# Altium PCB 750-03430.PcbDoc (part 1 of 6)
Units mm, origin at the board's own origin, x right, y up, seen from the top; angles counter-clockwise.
Board outline 141.61 x 63.5 mm, 6 copper layers (Top Layer, L2, L3, L4, L5, Bottom Layer), stack 1.557 mm thick; 401 components, 285 nets, 1356 pads, 1712 vias.
Unrouted connection lines stored in the file: 45.
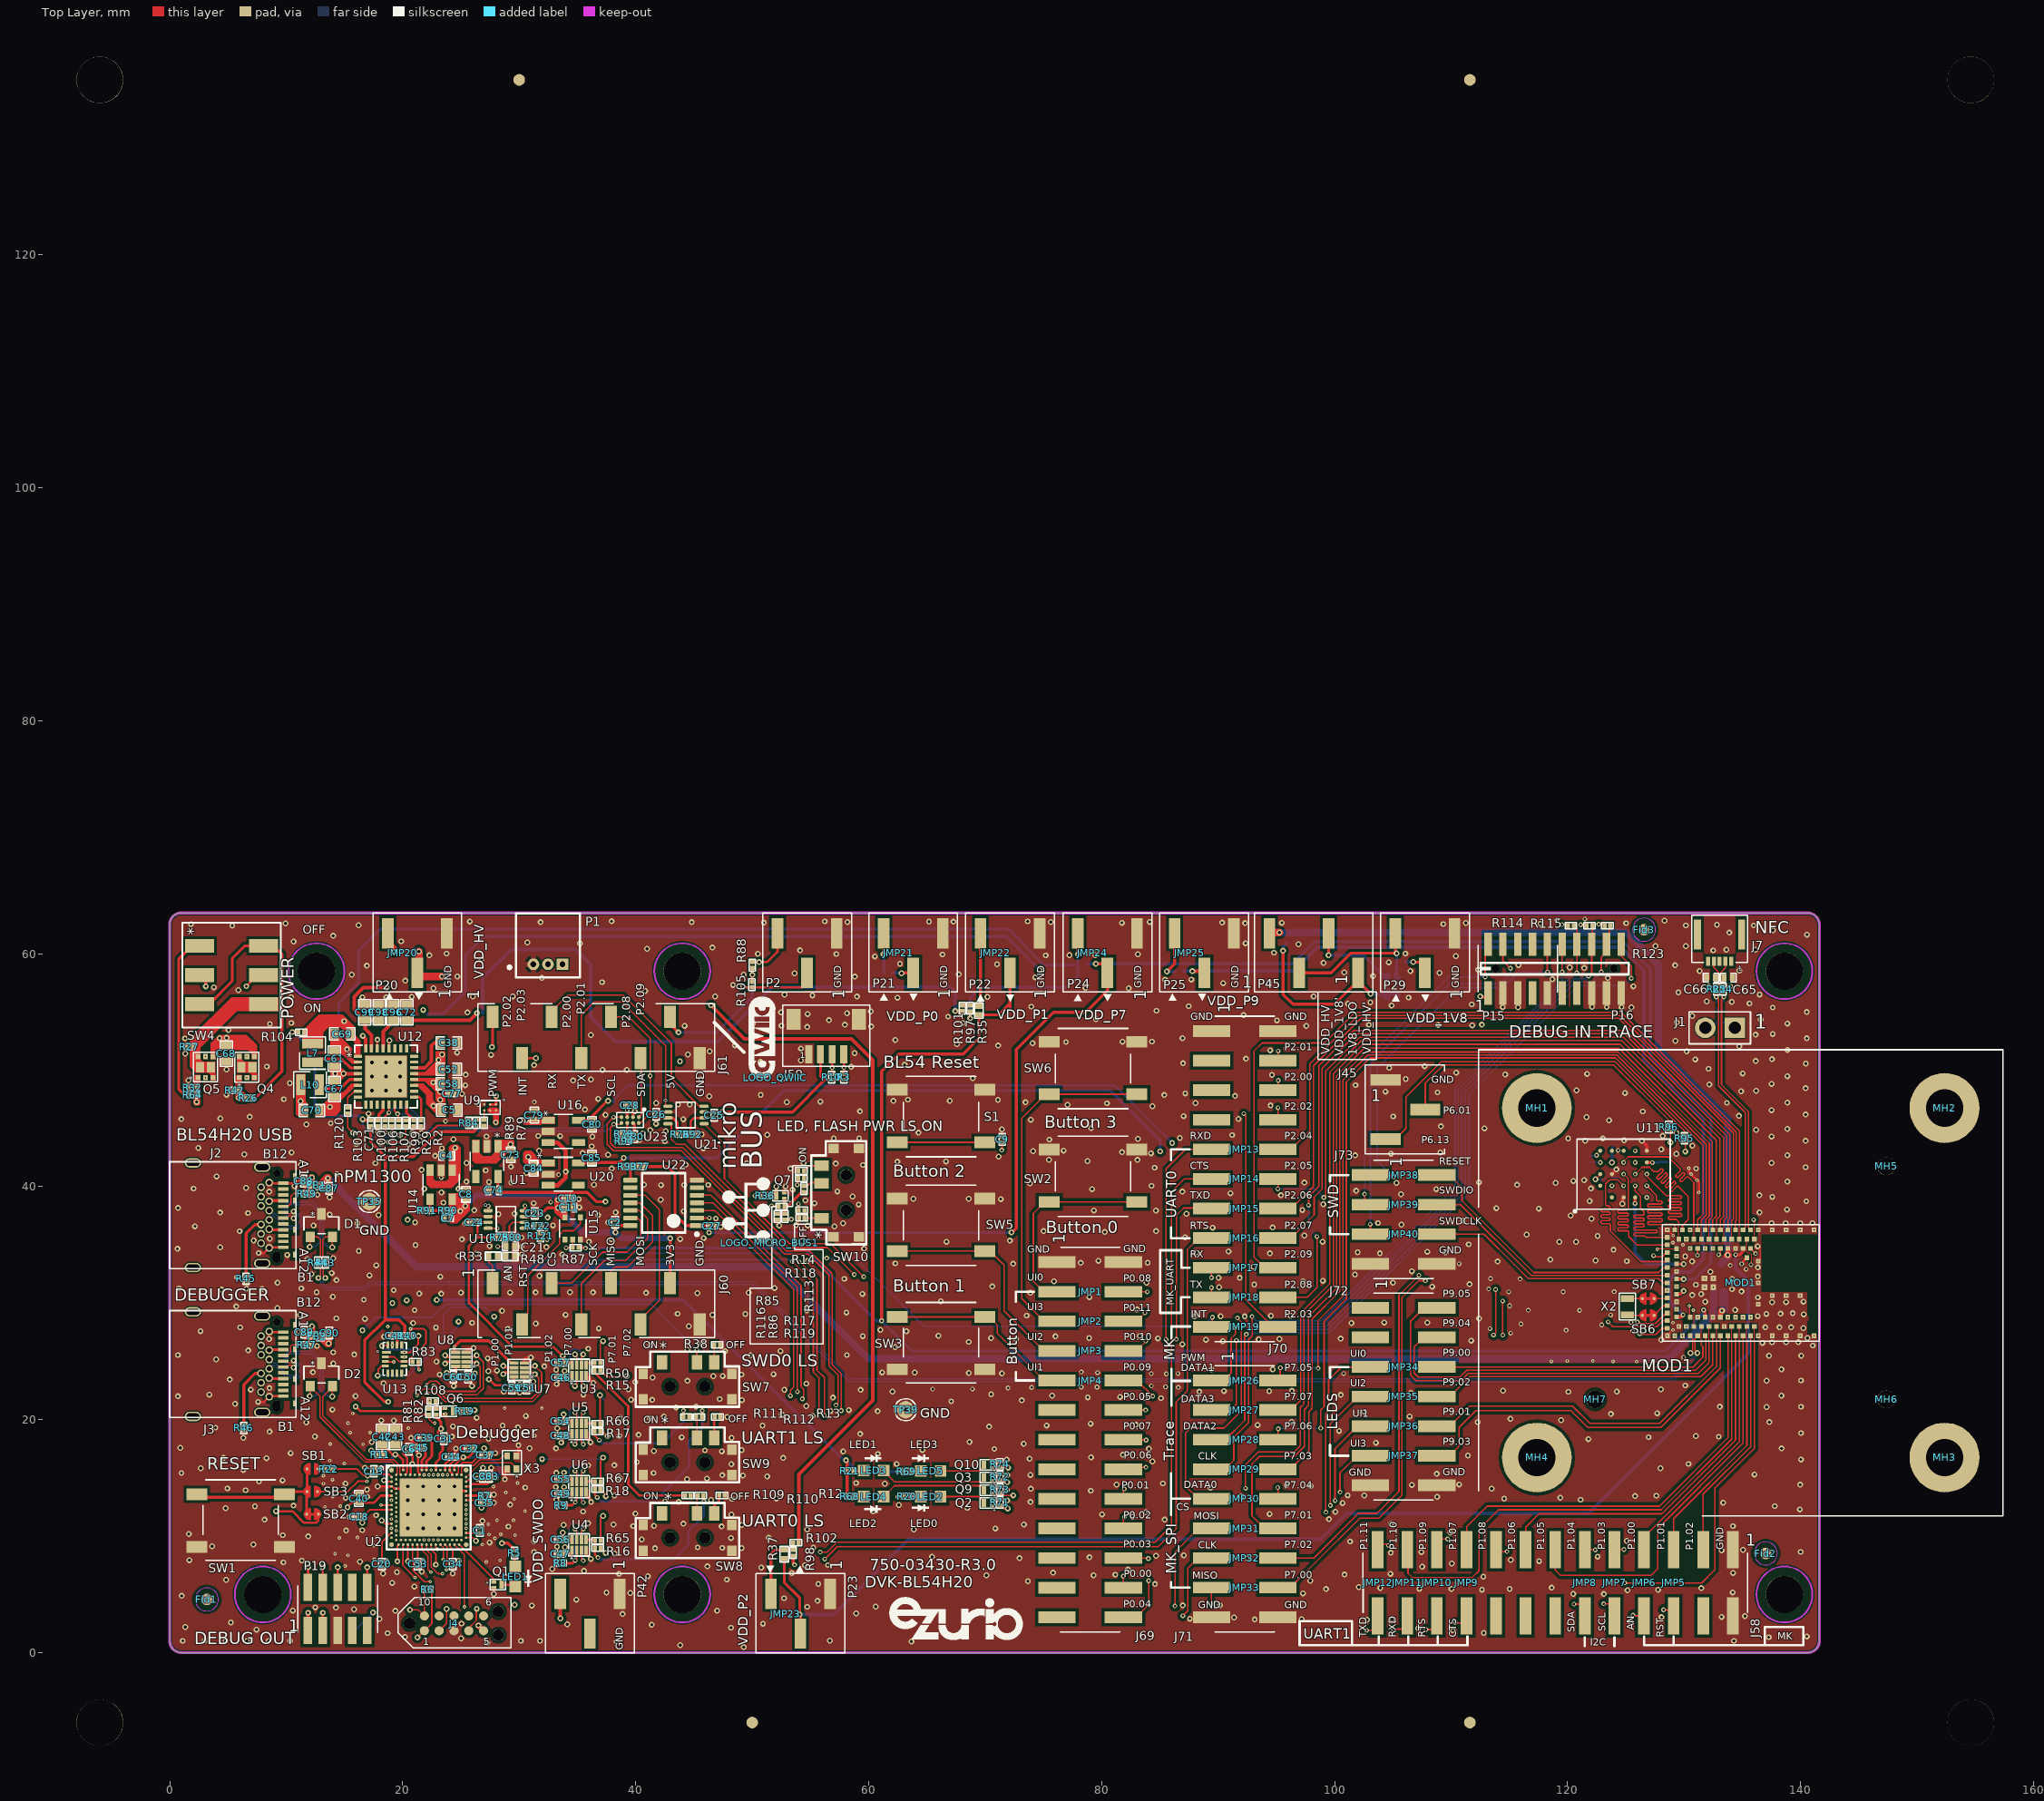
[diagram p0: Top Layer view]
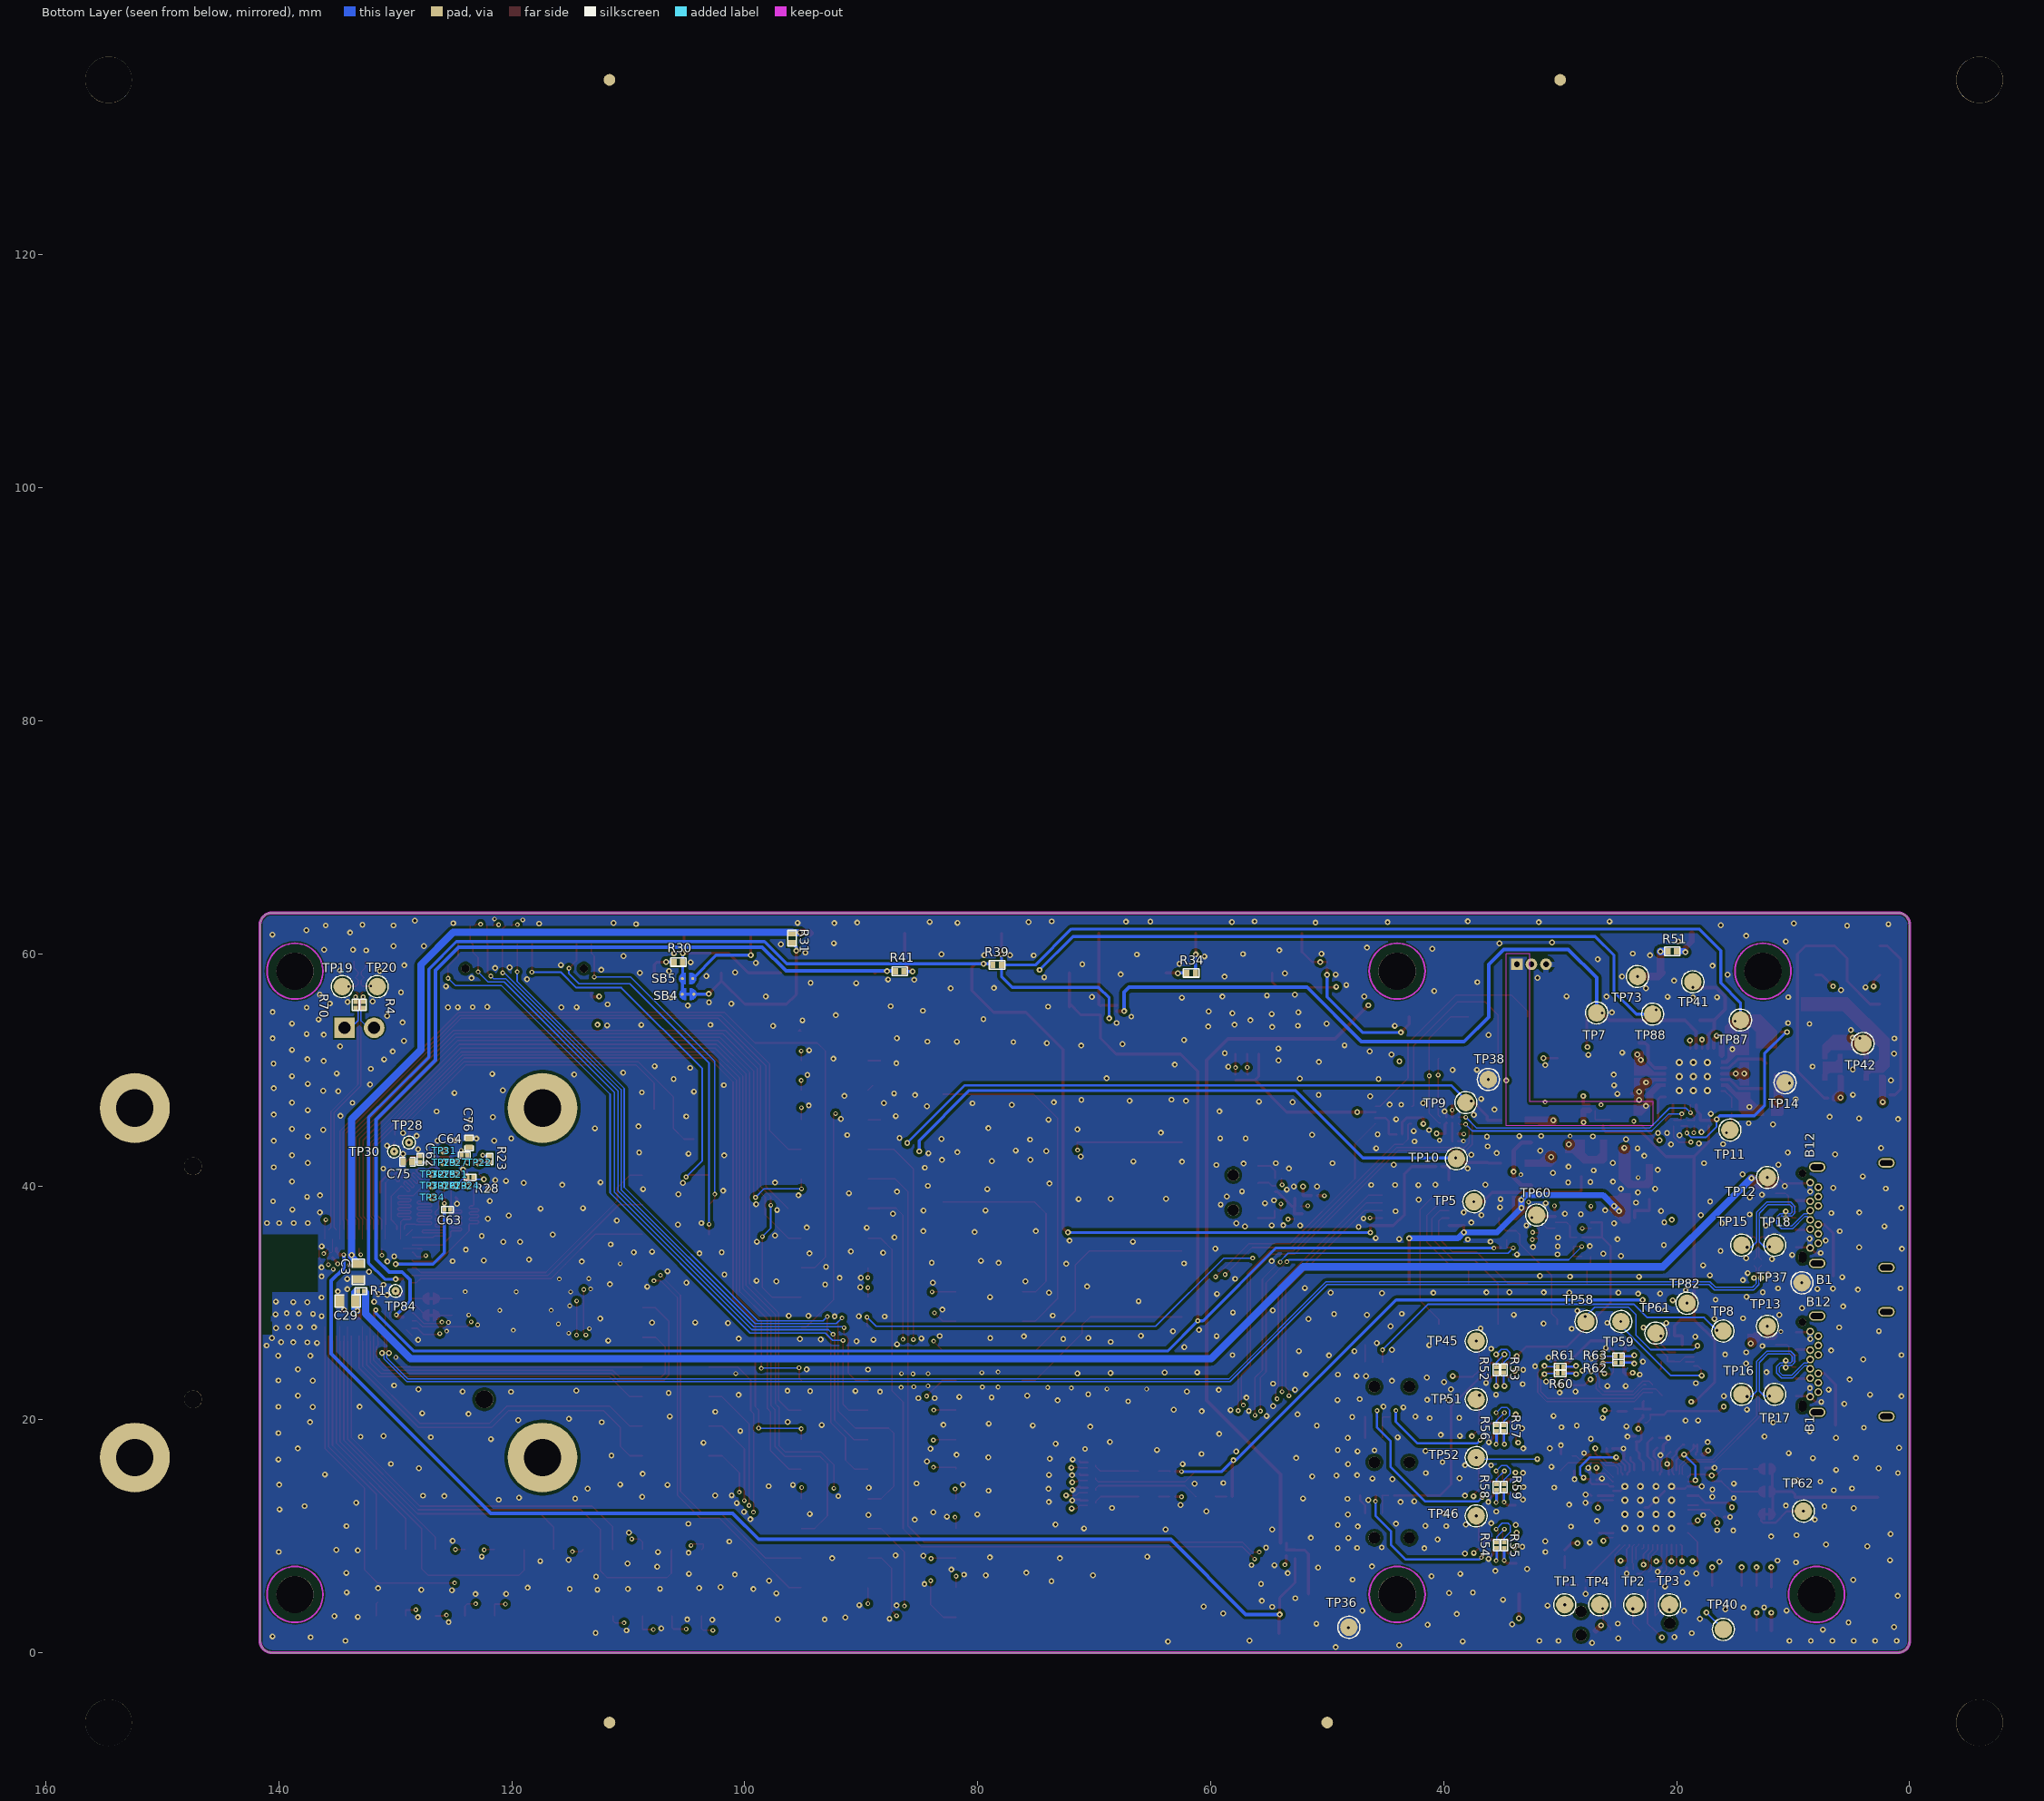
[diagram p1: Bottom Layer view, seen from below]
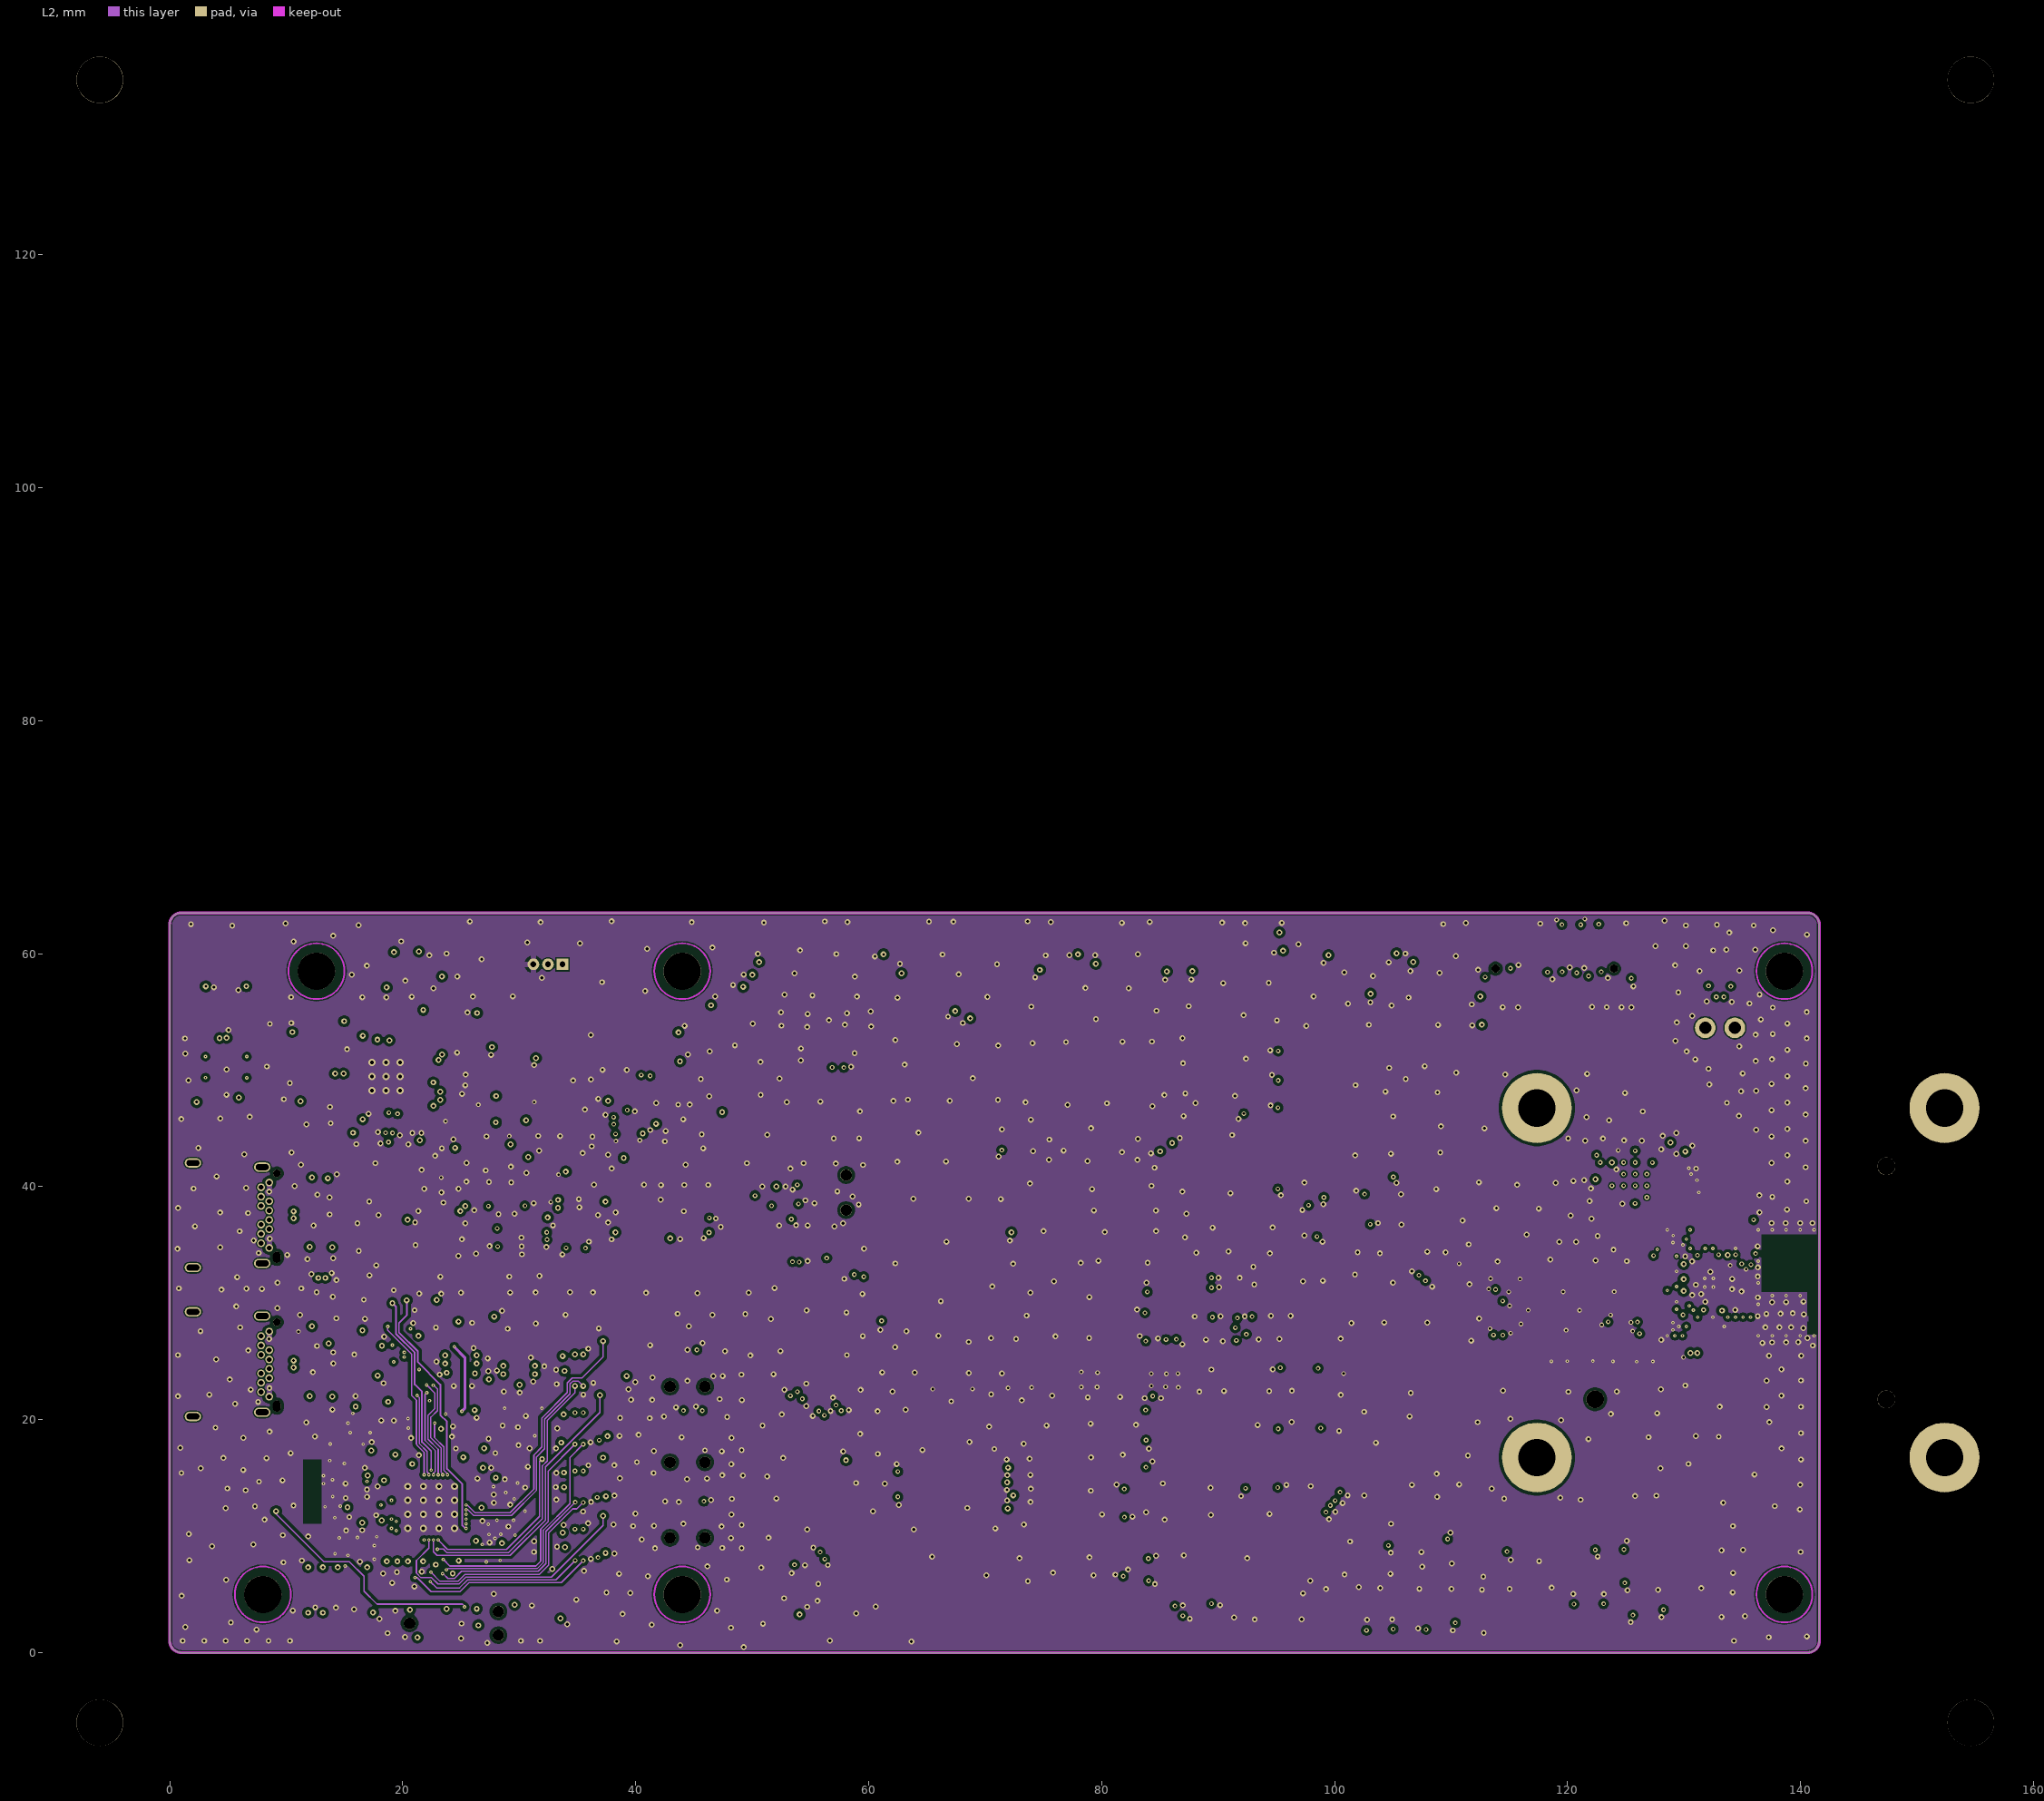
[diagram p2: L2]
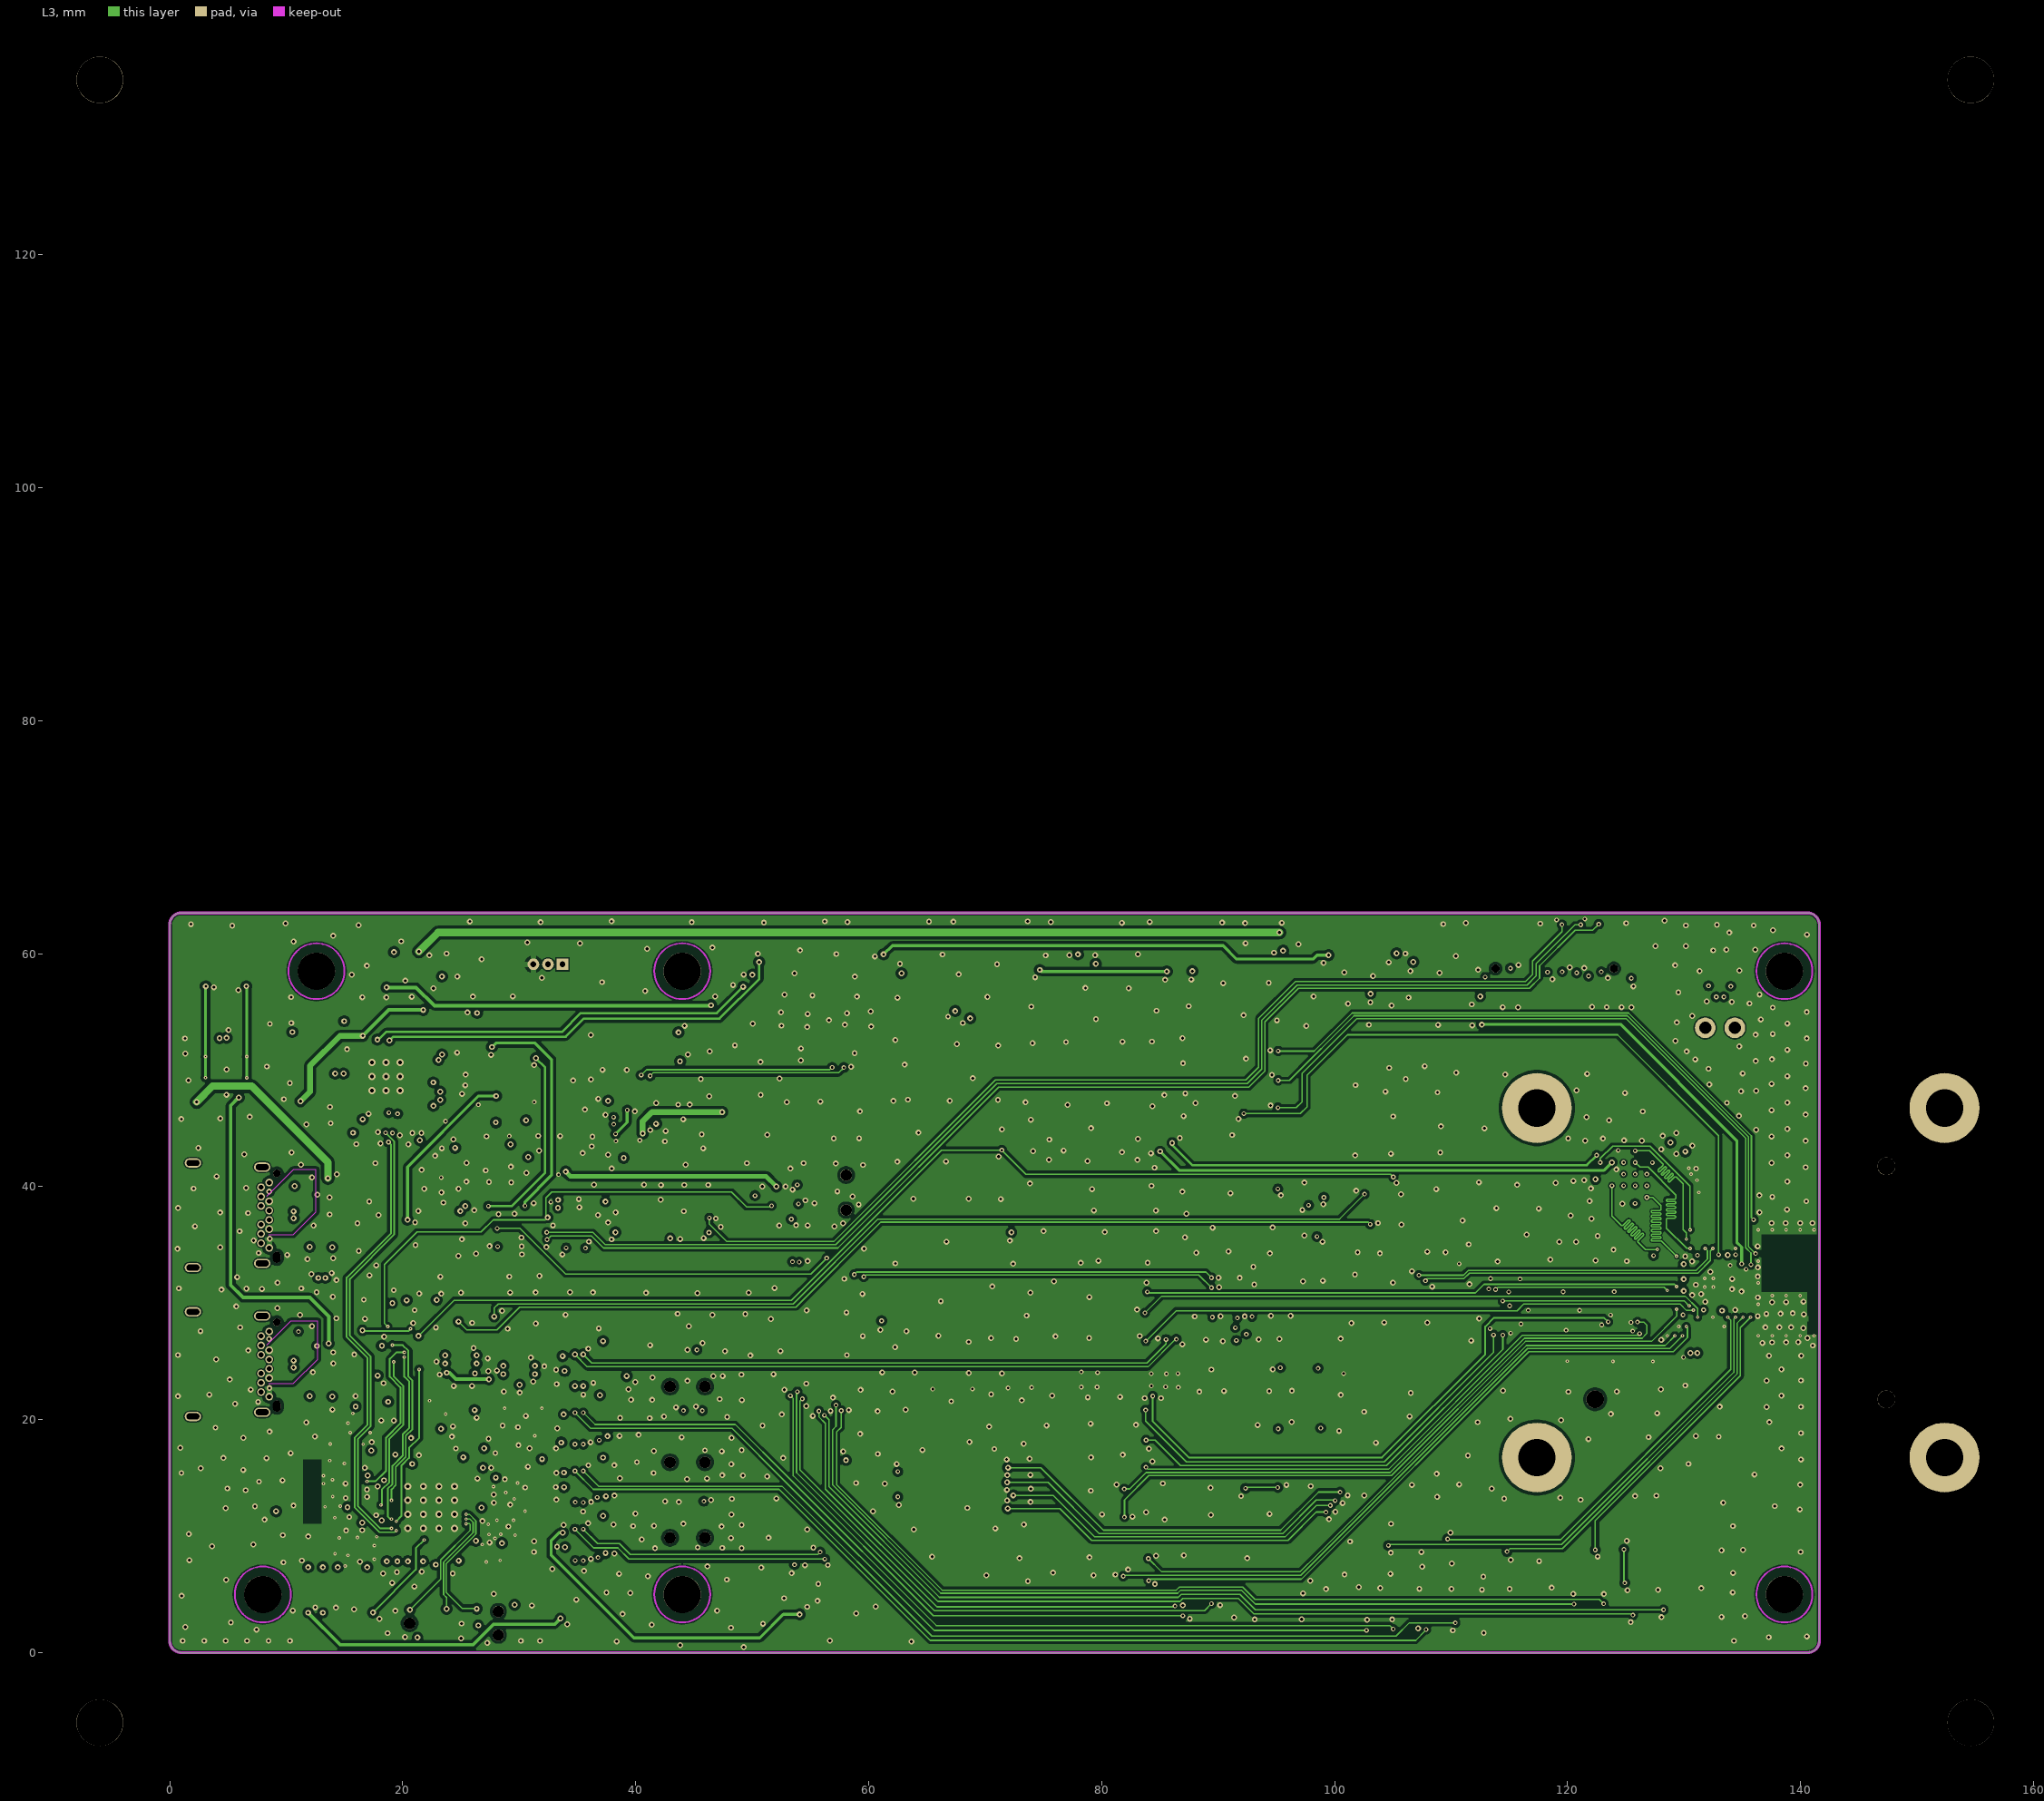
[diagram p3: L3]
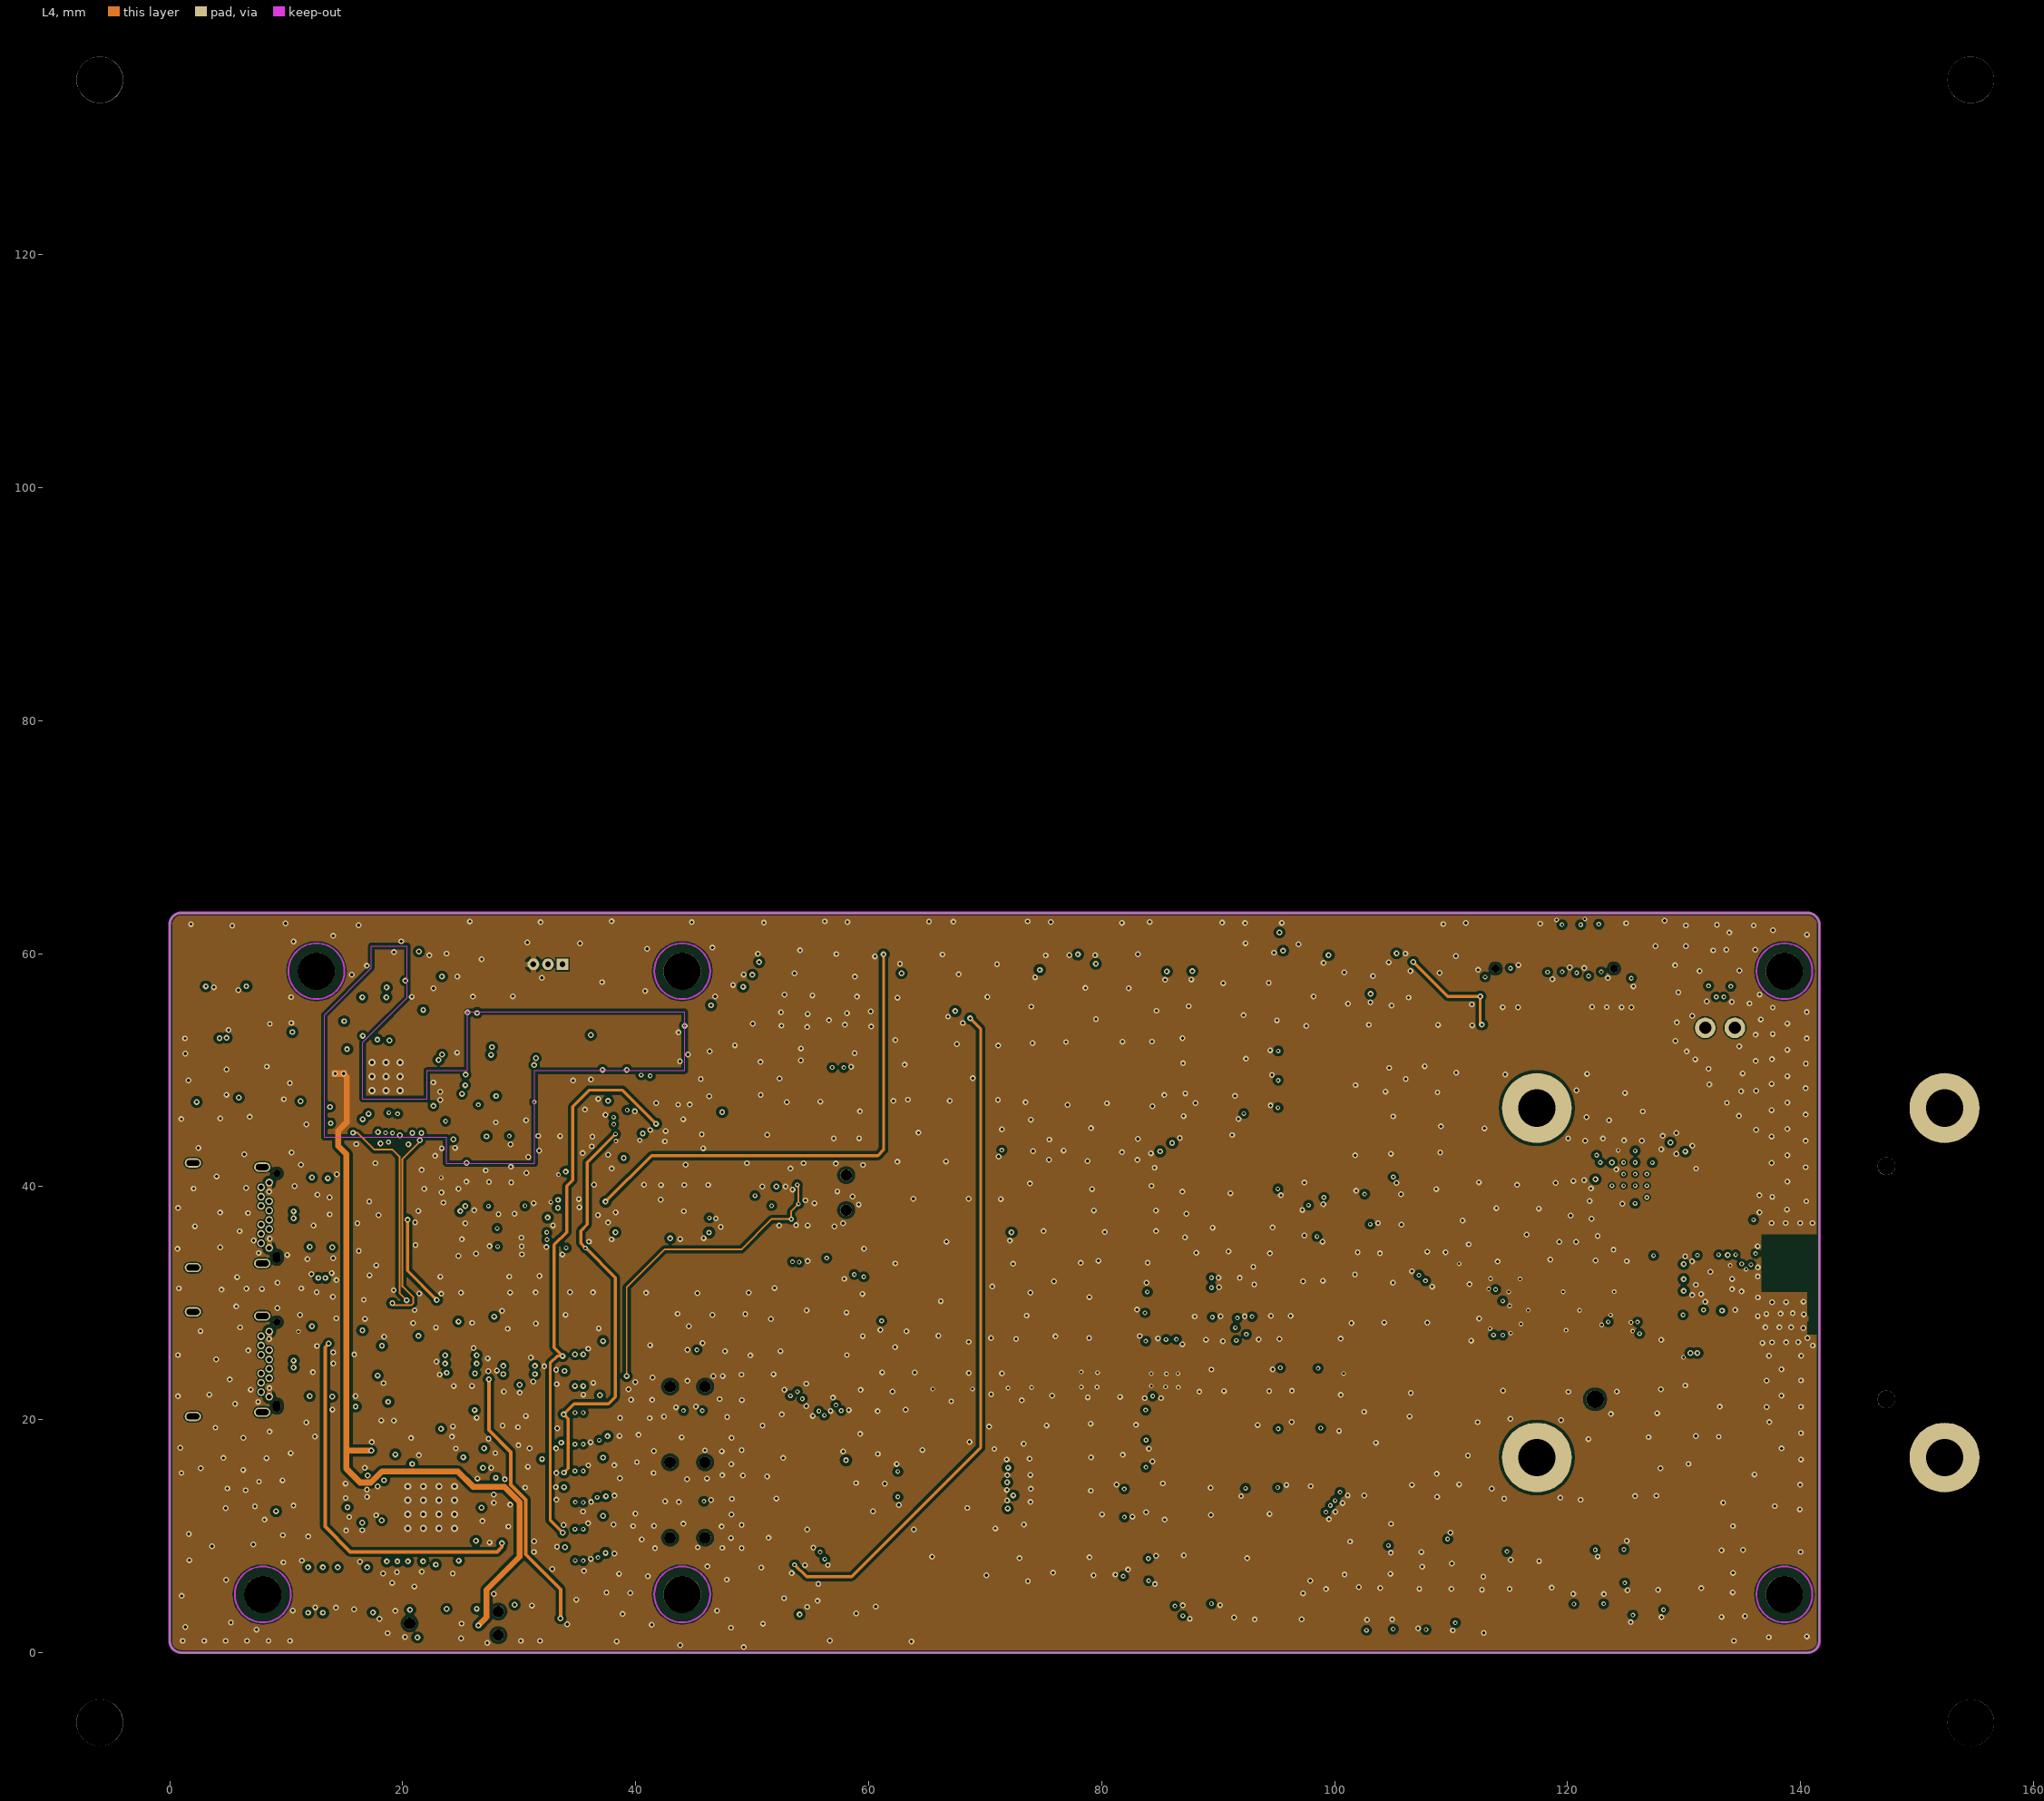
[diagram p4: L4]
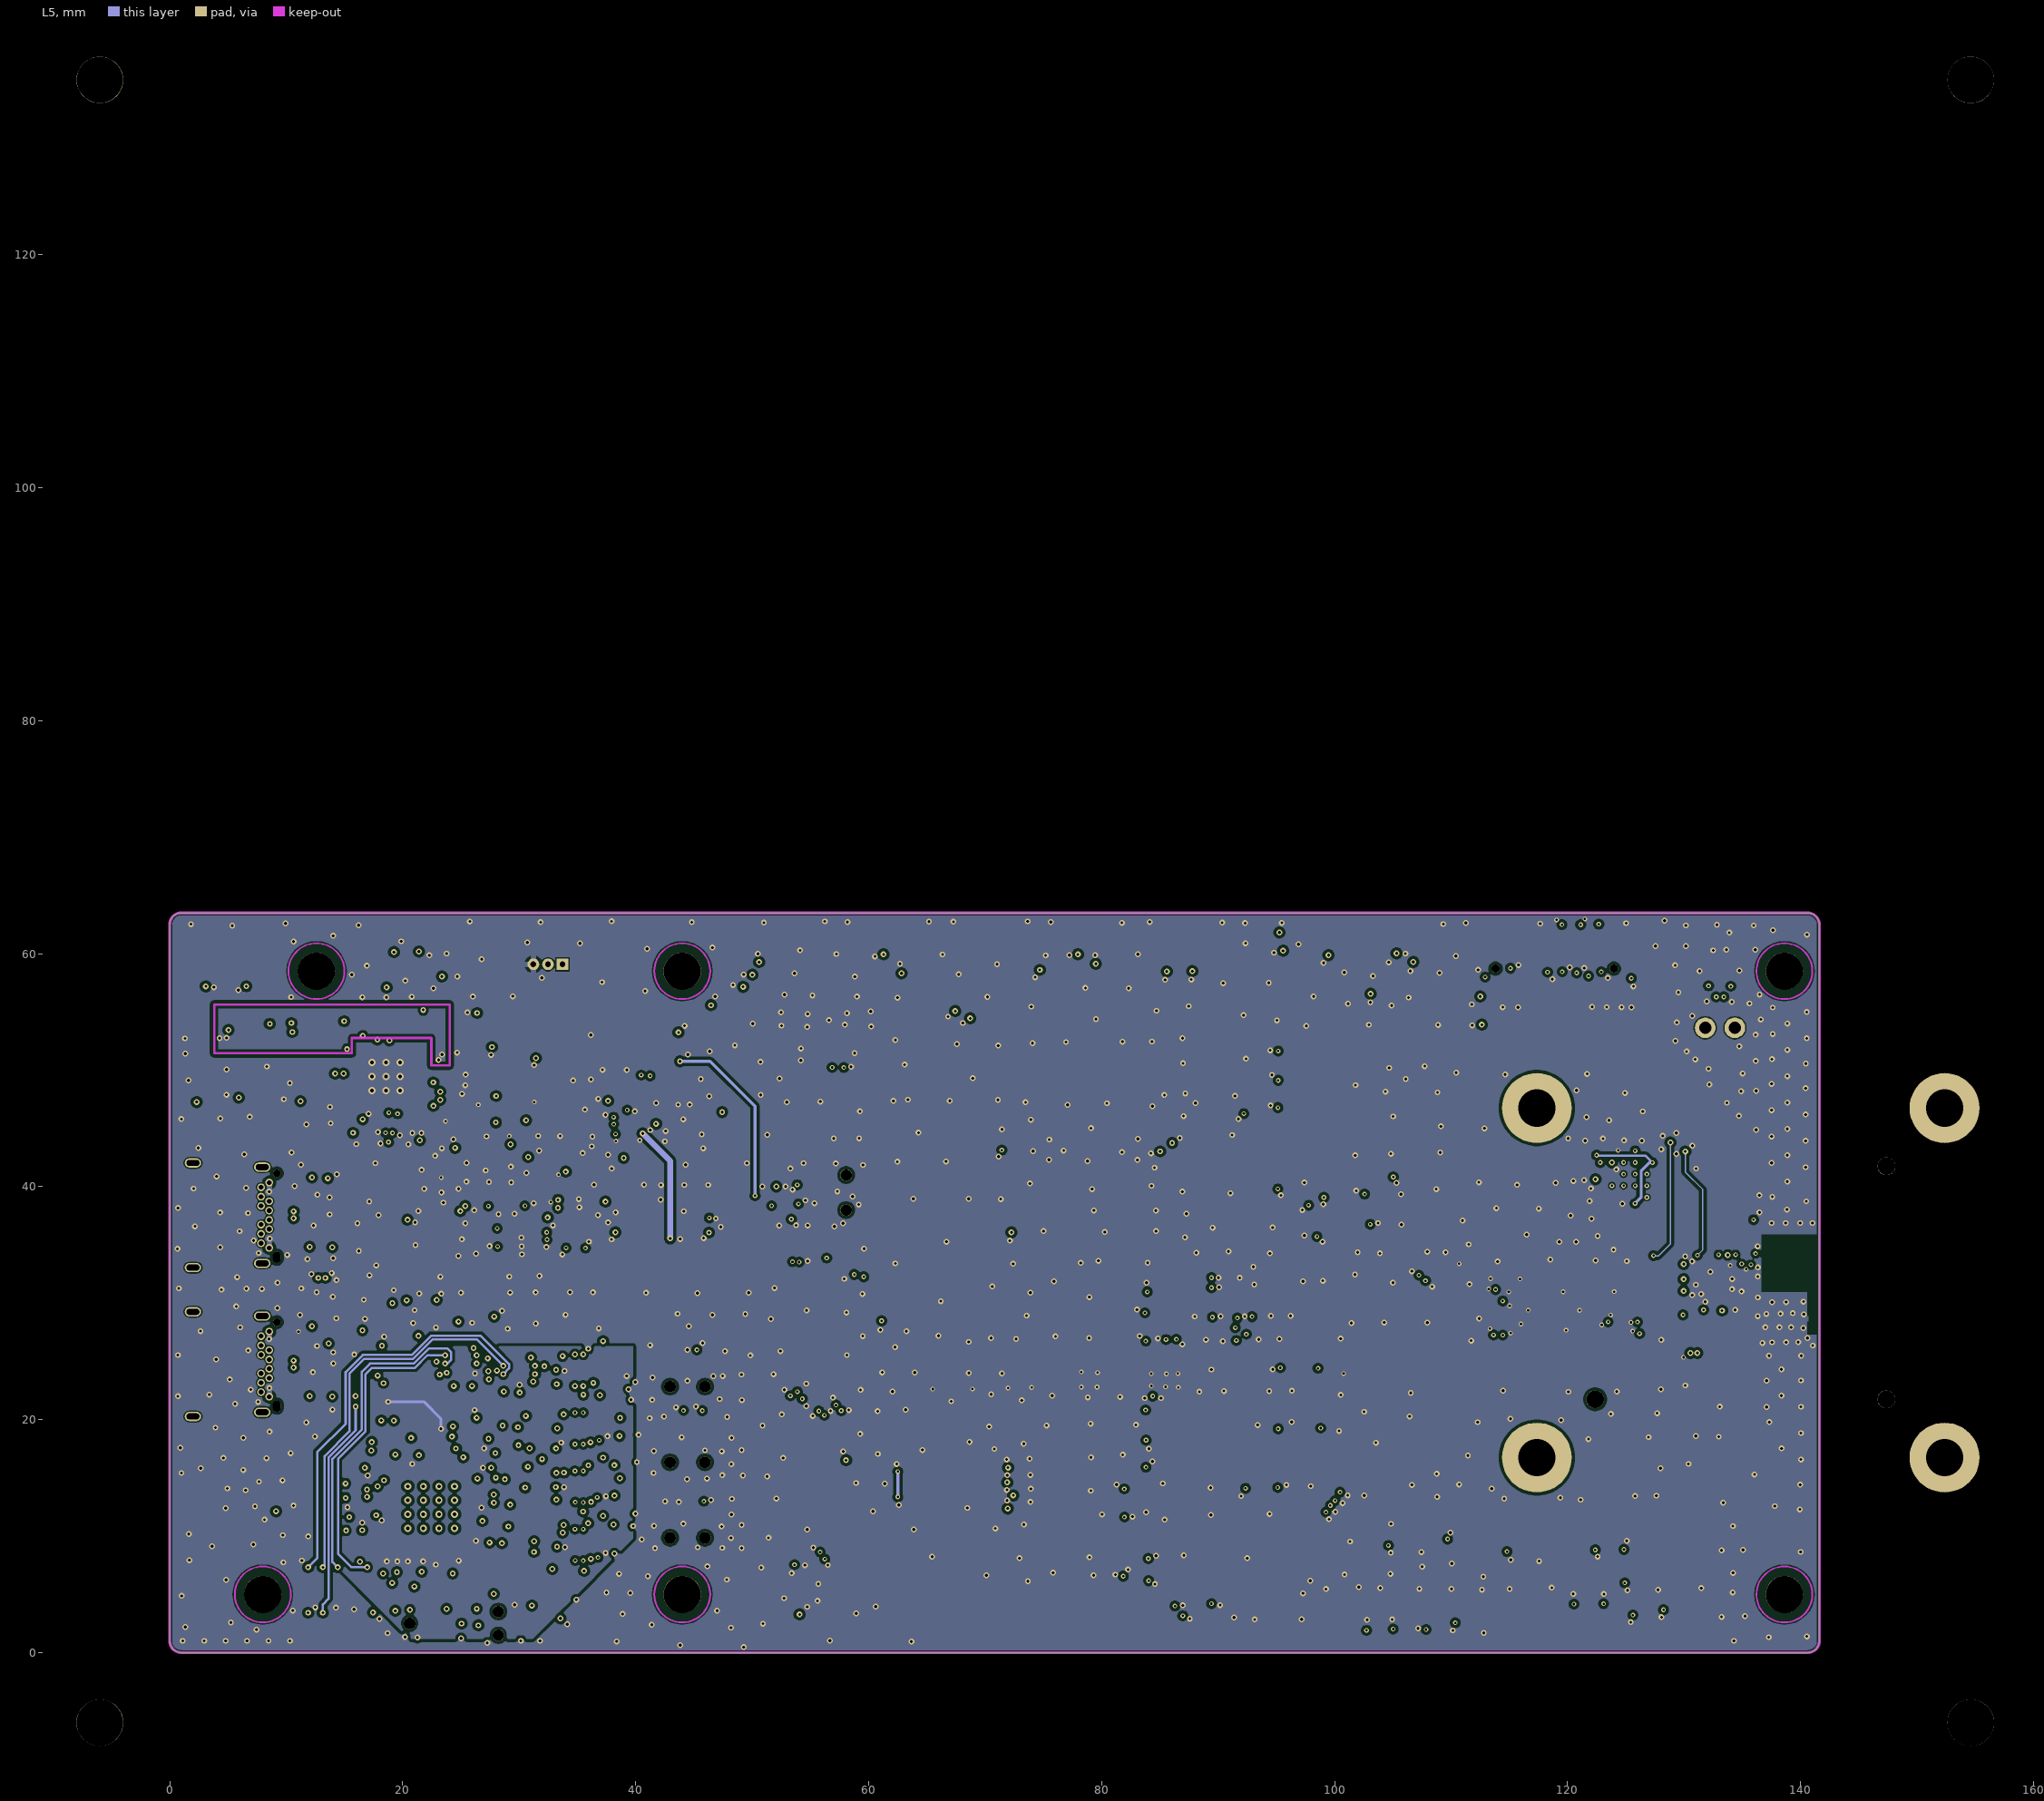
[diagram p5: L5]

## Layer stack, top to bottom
Top Solder: solder mask 0.0102, SM-003, Dk 3.5
Top Layer: signal copper 0.048
Dielectric 1: prepreg 0.084, PP-010, Dk 4
L2: signal copper 0.03
Dielectric 2: prepreg 0.081, PP-010, Dk 4
L3: signal copper 0.04
Dielectric 3: core 0.991, Core-042, Dk 4.6
L4: signal copper 0.04
Dielectric 4: prepreg 0.081, PP-010, Dk 4
L5: signal copper 0.03
Dielectric 5: prepreg 0.084, PP-010, Dk 4
Bottom Layer: signal copper 0.048
Bottom Solder: solder mask 0.0102, SM-003, Dk 3.5

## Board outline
0,1.016 0,62.484 -0.005,62.5 cw(c0.995,62.5) 0.995,63.5 140.593,63.5 cw(c140.593,62.484) 141.609,62.484 141.609,1.016 cw(c140.593,1.016) 140.593,0 1.016,0 cw(c1.016,1.016)

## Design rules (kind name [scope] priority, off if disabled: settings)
BoardOutlineClearance [All] p1 off: gap=0.508 ignorepadtopadclearanceinfootprint=FALSE except(0: Arc-SplitContinuation Track-SplitContinuation SMDPad-SplitContinuation THPad-SplitContinuation Via-SplitContinuation Fill-SplitContinuation Poly-SplitContinuation Region-SplitContinuation Text-OutlineEdge Text-SplitContinuation; 0.178: Track-OutlineEdge; 0.254: SMDPad-OutlineEdge Fill-OutlineEdge Poly-OutlineEdge Region-OutlineEdge; 0.762: Via-CavityEdge Via-CutoutEdge Via-SplitBarrior)
Clearance Clearance_ROOM [WithinRoom('RoomDefinition_1') vs OnTopLayer] p1: gap=0.076 ignorepadtopadclearanceinfootprint=TRUE
Clearance "Clearance_Flash Memory" [InNetClass('Flash Memory')] p2: gap=0.127 ignorepadtopadclearanceinfootprint=TRUE
Clearance Clearance_MOD1 [AsMils (ViaDiameter) = 8 vs AsMils (ViaDiameter) = 8] p3: gap=0.12 ignorepadtopadclearanceinfootprint=TRUE
Clearance Clearance_MicroVia_0.25 [AsMM(ViaDiameter) = 0.25 vs AsMM(ViaDiameter) = 0.25] p4: gap=0.1 ignorepadtopadclearanceinfootprint=FALSE except(0: Arc-Hole Track-Hole SMDPad-Hole THPad-Hole Via-Hole Fill-Hole Poly-Hole Region-Hole Text-Hole)
Clearance Clearance_MicroVia_0.30 [AsMM(ViaDiameter) = 0.30 vs AsMM(ViaDiameter) = 0.30] p5: gap=0.1 ignorepadtopadclearanceinfootprint=FALSE except(0: Arc-Hole Track-Hole SMDPad-Hole THPad-Hole Via-Hole Fill-Hole Poly-Hole Region-Hole Text-Hole)
Clearance Clearance_MicroVia_0.20 [AsMM(ViaDiameter) = 0.20 vs AsMM(ViaDiameter) = 0.20] p6: gap=0.1 ignorepadtopadclearanceinfootprint=FALSE except(0: Arc-Hole Track-Hole SMDPad-Hole THPad-Hole Via-Hole Fill-Hole Poly-Hole Region-Hole Text-Hole)
Clearance Polygon_Clearance [InPolygon vs OnTopLayer or OnMid or OnBottomLayer or IsVia] p7: gap=0.254 ignorepadtopadclearanceinfootprint=FALSE except(0: Arc-Hole Track-Hole SMDPad-Hole THPad-Hole Via-Hole Fill-Hole Poly-Hole Region-Hole Text-Hole)
Clearance Clearance_NPTH [(HoleDiameter > 0) and (PadIsPlated = 'False')] p8: gap=0.254 ignorepadtopadclearanceinfootprint=TRUE
Clearance Clearance_TopLayer [OnTopLayer] p9: gap=0.094 ignorepadtopadclearanceinfootprint=TRUE
Clearance [All] p10: gap=0.1 ignorepadtopadclearanceinfootprint=TRUE
Clearance Clearance_Diffpairs [InDifferentialPairClass('IMCU') or InDifferentialPairClass('nRF54') or InDifferentialPairClass('USB_CONN')] p11: gap=0.12 ignorepadtopadclearanceinfootprint=TRUE except(0.152: Via-Via)
ComponentClearance [All] p1 off: gap=0.254 collisioncheckmode=3 verticalgap=0.254 showdistances=FALSE
DiffPairsRouting DiffPair_USB_NRF54 [InDifferentialPair('USB_NRF54')] p1: maxlimit=0.127 minlimit=0.102 mostfreqgap=0.127 toplayer_maxgap=0.102 toplayer_prefgap=0.102 toplayer_minwidth=0.119 toplayer_maxwidth=0.119 toplayer_prefwidth=0.119 midlayer1_mingap=0.127 midlayer1_minwidth=0.058 midlayer1_maxwidth=0.058 midlayer1_prefwidth=0.058 midlayer2_mingap=0.127 midlayer2_minwidth=0.062 midlayer2_maxwidth=0.062 midlayer2_prefwidth=0.062 midlayer3_mingap=0.127 midlayer3_minwidth=0.062 midlayer3_maxwidth=0.062 midlayer3_prefwidth=0.062 midlayer4_mingap=0.127 midlayer4_minwidth=0.058 midlayer4_maxwidth=0.058 midlayer4_prefwidth=0.058 bottomlayer_maxgap=0.102 bottomlayer_prefgap=0.102 bottomlayer_minwidth=0.119 bottomlayer_maxwidth=0.119 bottomlayer_prefwidth=0.119 impedanceprofiledriven=TRUE impedanceprofileid={47E57DF5-D610-48AB-8B5C-E496585F7ABC} impedanceprofilevalue=90.000000 maxuncoupledlength=12.7
DiffPairsRouting DiffPair_USB_DBGR [InDifferentialPair('USB_DBGR')] p2: maxlimit=0.127 minlimit=0.102 mostfreqgap=0.127 toplayer_maxgap=0.102 toplayer_prefgap=0.102 toplayer_minwidth=0.119 toplayer_maxwidth=0.119 toplayer_prefwidth=0.119 midlayer1_mingap=0.127 midlayer1_minwidth=0.058 midlayer1_maxwidth=0.058 midlayer1_prefwidth=0.058 midlayer2_mingap=0.127 midlayer2_minwidth=0.062 midlayer2_maxwidth=0.062 midlayer2_prefwidth=0.062 midlayer3_mingap=0.127 midlayer3_minwidth=0.062 midlayer3_maxwidth=0.062 midlayer3_prefwidth=0.062 midlayer4_mingap=0.127 midlayer4_minwidth=0.058 midlayer4_maxwidth=0.058 midlayer4_prefwidth=0.058 bottomlayer_maxgap=0.102 bottomlayer_prefgap=0.102 bottomlayer_minwidth=0.119 bottomlayer_maxwidth=0.119 bottomlayer_prefwidth=0.119 impedanceprofiledriven=TRUE impedanceprofileid={47E57DF5-D610-48AB-8B5C-E496585F7ABC} impedanceprofilevalue=90.000000 maxuncoupledlength=12.7
DiffPairsRouting DiffPair_D [InDifferentialPair('D')] p3: maxlimit=0.127 minlimit=0.102 mostfreqgap=0.127 toplayer_maxgap=0.102 toplayer_prefgap=0.102 toplayer_minwidth=0.119 toplayer_maxwidth=0.119 toplayer_prefwidth=0.119 midlayer1_mingap=0.127 midlayer1_minwidth=0.058 midlayer1_maxwidth=0.058 midlayer1_prefwidth=0.058 midlayer2_mingap=0.127 midlayer2_minwidth=0.062 midlayer2_maxwidth=0.062 midlayer2_prefwidth=0.062 midlayer3_mingap=0.127 midlayer3_minwidth=0.062 midlayer3_maxwidth=0.062 midlayer3_prefwidth=0.062 midlayer4_mingap=0.127 midlayer4_minwidth=0.058 midlayer4_maxwidth=0.058 midlayer4_prefwidth=0.058 bottomlayer_maxgap=0.102 bottomlayer_prefgap=0.102 bottomlayer_minwidth=0.119 bottomlayer_maxwidth=0.119 bottomlayer_prefwidth=0.119 impedanceprofiledriven=TRUE impedanceprofileid={47E57DF5-D610-48AB-8B5C-E496585F7ABC} impedanceprofilevalue=90.000000 maxuncoupledlength=12.7
FabricationTestPointUsage TestPointUsage [All] p1: valid=0 allowmultiple=FALSE
FabricationTestpoint Testpoint [All] p1: side=3 testpointundercomponent=TRUE minsize=1.016 maxsize=2.54 preferedsize=1.524 minholesize=0 maxholesize=1.016 preferedholesize=0.813 testpointgrid=0.025 allowsidetop=TRUE allowsidebottom=TRUE usegrid=TRUE gridtolerance=0
Height [All] p1 off: minheight=0 maxheight=25.4 prefheight=12.7
HoleSize [All] p1: absolutevalues=TRUE maxlimit=5 minlimit=0.1 maxpercent=80.000 minpercent=20.000
MatchedLengths DiffPair_USB_NRF_1 [InDifferentialPair ('USB_NRF54')] p1: tolerance=25.4 checknetsindiffpair=FALSE checkdiffpairvsdiffpair=TRUE checkxsignals=TRUE checkothers=TRUE
MatchedLengths DiffPair_USB_DBGR_1 [InDifferentialPair ('USB_DBGR')] p2: tolerance=25.4 checknetsindiffpair=FALSE checkdiffpairvsdiffpair=TRUE checkxsignals=TRUE checkothers=TRUE
MatchedLengths DiffPair_D_1 [InDifferentialPair ('D')] p3: tolerance=25.4 checknetsindiffpair=FALSE checkdiffpairvsdiffpair=TRUE checkxsignals=TRUE checkothers=TRUE
MatchedLengths MatchedLengths_1 [InDifferentialPair ('USB_NRF54')] p4: tolerance=25.4 checknetsindiffpair=FALSE checkdiffpairvsdiffpair=TRUE checkxsignals=TRUE checkothers=TRUE
MatchedLengths [InDifferentialPairClass('Module')] p5: tolerance=25.4 checknetsindiffpair=FALSE checkdiffpairvsdiffpair=TRUE checkxsignals=TRUE checkothers=TRUE
MinimumAnnularRing [All] p1 off: minimumring=0.152
MinimumSolderMaskSliver [All] p1 off: minsoldermaskwidth=0.076
MinimumSolderMaskSliver MinimumSolderMaskSliver_1 [IsPad vs SolderMaskExpansionFromHoleEdge] p2 off: minsoldermaskwidth=0.2
PolygonConnect PolygonConnect_Header [InComponentClass('Header') vs InNet('GND')] p1: connectstyle=Relief reliefconductorwidth=0.508 reliefentries=4 polygonreliefangle="90 Angle" airgapwidth=0.254
PolygonConnect [All] p2: connectstyle=Direct reliefconductorwidth=0.254 reliefentries=4 polygonreliefangle="90 Angle" airgapwidth=0.254
RoomDefinition RoomDefinition_1 [False vs False] p1: confinementstyle=ConfineIn formatcopy=TRUE lockcomponents=FALSE outline 128.359,36.5 141.35,36.5 141.35,27 128.359,27
RoutingVias RoutingVias_Buried [InDrillLayerPair('Mid-Layer 2 - Mid-Layer 3')] p1: holewidth=0.711 width=1.27 viastyle="Through Hole" minholewidth=0.711 minwidth=1.27 maxholewidth=0.711 maxwidth=1.27 useviatemplates=TRUE viatemplateguid#1={DAE5EB1E-7558-4805-82C6-1DEB710AA66E} viatemplatename#1=v30h15m0mx0
RoutingVias RoutingVias_Buried_Laser [InDrillLayerPair('Mid-Layer 1 - Mid-Layer 2') or  InDrillLayerPair('Mid-Layer 3 - Mid-Layer 4')] p2: holewidth=0.711 width=1.27 viastyle="Through Hole" minholewidth=0.711 minwidth=1.27 maxholewidth=0.711 maxwidth=1.27 useviatemplates=TRUE viatemplateguid#1={B4878FE1-FE08-41AA-B7EE-3AC84FE0193A} viatemplatename#1=v30h10m0
RoutingVias RoutingVias_Blind [IsBlindVia] p3: holewidth=0.711 width=1.27 viastyle="Through Hole" minholewidth=0.711 minwidth=1.27 maxholewidth=0.711 maxwidth=1.27 useviatemplates=TRUE viatemplateguid#1={36B61C82-F293-447D-B46A-9404988606FE} viatemplateguid#2={B4878FE1-FE08-41AA-B7EE-3AC84FE0193A} viatemplatename#1=v20h10 viatemplatename#2=v30h10m0
RoutingVias RoutingVias_thru [IsThruVia] p4: holewidth=0.305 width=0.61 viastyle="Through Hole" minholewidth=0.305 minwidth=0.61 maxholewidth=0.711 maxwidth=1.27 useviatemplates=TRUE viatemplateguid#1={82036E38-F072-4C30-A6BC-624A27519C39} viatemplateguid#2={462064FF-42C7-473E-A651-561C1576AFDF} viatemplatename#1=v40h20m0mx0 viatemplatename#2=v50h25m0mx0
ShortCircuit ShortCircuit_2 [InNet('PVSS1')or InNet('PVSS2') vs InNet('GND')] p1: allowed=TRUE
ShortCircuit ShortCircuit_1 [InComponent('P16') vs InComponent('P15')] p2: allowed=TRUE
ShortCircuit [All] p3: allowed=FALSE
SilkToSilkClearance [All] p1 off: silktosilkclearance=0.254
SilkToSolderMaskClearance SilkscreenOverComponentPads [IsPad] p1 off: minsilkscreentomaskgap=0.254 clearancetoexposedcopper=TRUE
SolderMaskExpansion SolderMaskExpansion_nRF54 [HasFootprint('BGA115C35P12X12_468X428X51')] p1: expansion=0 istentingtop=FALSE
SolderMaskExpansion SolderMaskExpansion_footprints [HasFootprint('UDFN65P200X200X60_HS-6N') or HasFootprint('SON50P300X80-HS-11N') or HasFootprint('US8') or HasFootprint('SON50P300X80_HS-9N') or HasFootprint('BGA25C40P5X5_200X200X50') or HasFootprint('QFN40P180X140X55-10N') or HasFootprint('DX07S016JA1R1500') or HasFootprint('AQFN40P700X700X85_HS-99N')] p2: expansion=0.04 istentingtop=FALSE
SolderMaskExpansion SolderMaskExpansion_VIA [IsVia] p3: expansion=0.076 istentingtop=TRUE
SolderMaskExpansion [All] p4: expansion=0.076 istentingtop=FALSE
SupplyNets "Schematic Supply Nets_26" [InNet('VDD_P9')] p1: voltage=0.000
SupplyNets "Schematic Supply Nets_25" [InNet('VCC_1V8')] p2: voltage=0.000
SupplyNets "Schematic Supply Nets_24" [InNet('VDD_P1')] p3: voltage=0.000
SupplyNets "Schematic Supply Nets_23" [InNet('VCCQ_1V8')] p4: voltage=0.000
SupplyNets "Schematic Supply Nets_22" [InNet('5V0')] p5: voltage=0.000
SupplyNets "Schematic Supply Nets_21" [InNet('VDD_P7')] p6: voltage=0.000
SupplyNets "Schematic Supply Nets_20" [InNet('VOUT1')] p7: voltage=0.000
SupplyNets "Schematic Supply Nets_19" [InNet('P3V3')] p8: voltage=0.000
SupplyNets "Schematic Supply Nets_18" [InNet('VDD_SWD0')] p9: voltage=0.000
SupplyNets "Schematic Supply Nets_17" [InNet('VDD_P2')] p10: voltage=0.000
SupplyNets "Schematic Supply Nets_16" [InNet('1V8_LDO')] p11: voltage=0.000
SupplyNets "Schematic Supply Nets_15" [InNet('GND')] p12: voltage=0.000
SupplyNets "Schematic Supply Nets_14" [InNet('VDD_HV')] p13: voltage=0.000
SupplyNets "Schematic Supply Nets_13" [InNet('VBUS')] p14: voltage=0.000
SupplyNets "Schematic Supply Nets_12" [InNet('VOUT2')] p15: voltage=0.000
SupplyNets "Schematic Supply Nets_10" [InNet('VBUS_nRF')] p16: voltage=0.000
SupplyNets "Schematic Supply Nets_9" [InNet('VDD_1V8')] p17: voltage=0.000
SupplyNets "Schematic Supply Nets_7" [InNet('VOUTLDO1')] p18: voltage=0.000
SupplyNets "Schematic Supply Nets_6" [InNet('VDD_P0')] p19: voltage=0.000
SupplyNets "Schematic Supply Nets_5" [InNet('VDD_DBGR')] p20: voltage=0.000
SupplyNets "Schematic Supply Nets_4" [InNet('VOUTLDO2')] p21: voltage=0.000
SupplyNets "Schematic Supply Nets_3" [InNet('VBUS_DBGR')] p22: voltage=0.000
SupplyNets "Schematic Supply Nets_2" [InNet('PVSS1')] p23: voltage=0.000
SupplyNets "Schematic Supply Nets_1" [InNet('5V0_LED')] p24: voltage=0.000
SupplyNets "Schematic Supply Nets" [InNet('PVSS2')] p25: voltage=0.000
UnRoutedNet [All] p1: checkbadconnections=TRUE
ViasUnderSMD ViasUnderSMD_bga [IsBGA] p1: allowed=TRUE
ViasUnderSMD [All] p2: allowed=TRUE
Width Width_ROOM [WithinRoom('RoomDefinition_1') and OnTopLayer] p1: maxlimit=0.305 minlimit=0.076 preferedwidth=0.076
Width "Flash Memory" [InNetClass('Flash Memory')] p2: maxlimit=0.127 minlimit=0.054 preferedwidth=0.102 toplayer_minwidth=0.127 toplayer_prefwidth=0.127 midlayer1_maxwidth=0.054 midlayer1_prefwidth=0.054 midlayer2_minwidth=0.102 midlayer2_maxwidth=0.102 midlayer3_minwidth=0.102 midlayer3_maxwidth=0.102 midlayer4_maxwidth=0.054 midlayer4_prefwidth=0.054 bottomlayer_minwidth=0.127 bottomlayer_prefwidth=0.127 impedanceprofiledriven=TRUE impedanceprofileid={48E6739F-D61A-4A22-9A11-294F9CD65B7E} impedanceprofilevalue=50.000000 minimp=50.000000 maximp=50.000000 favimp=50.000000
Width Width_QSPI [InNetClass('xSPI')] p3: maxlimit=0.127 minlimit=0.054 preferedwidth=0.102 toplayer_minwidth=0.127 toplayer_prefwidth=0.127 midlayer1_maxwidth=0.054 midlayer1_prefwidth=0.054 midlayer2_minwidth=0.102 midlayer2_maxwidth=0.102 midlayer3_minwidth=0.102 midlayer3_maxwidth=0.102 midlayer4_maxwidth=0.054 midlayer4_prefwidth=0.054 bottomlayer_minwidth=0.127 bottomlayer_prefwidth=0.127 impedanceprofiledriven=TRUE impedanceprofileid={48E6739F-D61A-4A22-9A11-294F9CD65B7E} impedanceprofilevalue=50.000000 minimp=50.000000 maximp=50.000000 favimp=50.000000
Width [All] p4: maxlimit=2.54 minlimit=0.102 preferedwidth=0.152
19 further rules are at their usual default settings.

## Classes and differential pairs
component class Header: J2 J3 P1
net class "Flash Memory": P6.00/CK P6.02/RWDS P6.03/CS0 P6.04/DQ7 P6.05/DQ1 P6.06/DQ6 P6.07/DQ0 P6.08/DQ5 P6.10/DQ2
component class CS-DOC-000013317[History]: PCB1
component class U_CS-DOC-000013317[Debugger_MCU]: C1 C6 C13 C18 C20 C31 C32 C33 C34 C35 C36 C37 C39 C40 C42 C43 C44 C45 C53 J4 LED1 Q1 R5 R6 R7 R8 R9 R11 TP1 TP2 TP3 TP4 TP11 TP40 TP45 TP46 TP51 TP52 TP60 TP62 TP82 U2 X3
component class U_CS-DOC-000013317[Misc]: C62 C63 C64 C65 C66 C75 C76 LED2 LED3 LED4 LED5 Q2 Q3 Q9 Q10 R20 R21 R22 R23 R24 R25 R28 R68 R69 R71 R72 R73 R74 SB1 SW1 SW2 SW3 SW5 SW6 TP21 TP22 TP23 TP24 TP25 TP26 TP27 TP29 TP31 TP32 TP33 TP34 U11
net class USB: D_N D_P DBGR_N DBGR_P nRF54_N nRF54_P
component class U_CS-DOC-000013317[Power_Supply]: C5 C38 C52 C58 C61 C67 C68 C69 C70 C71 C72 C73 C74 C77 C79 C80 C84 C85 C96 C98 C99 JMP20 JMP21 JMP22 JMP23 JMP24 JMP25 L7 L10 P1 P2 P20 P21 P22 P23 P24 P25 P29 P45 Q4 Q5 Q7 R2 R14 R26 R27 R29 R30 R31 R32 R34 R35 R36 R37 R39 R41 R42 R51 R64 R79 R84 R85 R86 R88 R89 R97 R98 R99 R100 R101 R102 R103 R104 R105 R106 R107 R113 R116 R117 R118 R119 R120 SB4 SB5 SW4 SW10 TP5 TP7 TP9 TP10 TP14 TP35 TP36 TP37 TP38 TP39 TP41 TP42 TP73 TP87 TP88 U1 U9 U12 U16 U20
component class U_CS-DOC-000013317[Connectors]: C2 C4 C7 C8 C10 C11 C21 C23 C24 C25 C26 C27 C28 C30 C87 C88 C89 C90 D1 D2 FB1 FB2 J2 J3 J7 J59 J60 J61 P15 P16 P19 P42 R3 R10 R33 R43 R44 R45 R46 R47 R48 R49 R75 R76 R77 R78 R80 R87 R90 R91 R92 R93 R94 R114 R115 R121 R122 R123 TP12 TP13 TP15 TP16 TP17 TP18 TP19 TP20 U10 U14 U15 U21 U22 U23
component class U_CS-DOC-000013317[Level_Shifters]: C41 C46 C47 C48 C49 C50 C51 C54 C55 C56 C57 C59 C60 Q6 R12 R13 R15 R16 R17 R18 R19 R38 R40 R50 R52 R53 R54 R55 R56 R57 R58 R59 R60 R61 R62 R63 R65 R66 R67 R81 R82 R83 R108 R109 R110 R111 R112 SW7 SW8 SW9 TP8 TP58 TP59 TP61 U3 U4 U5 U6 U7 U8 U13
component class U_CS-DOC-000013317[BL54H20]: C3 C29 J1 J45 J58 J69 J70 J71 J72 J73 JMP1 JMP2 JMP3 JMP4 JMP5 JMP6 JMP7 JMP8 JMP9 JMP10 JMP11 JMP12 JMP13 JMP14 JMP15 JMP16 JMP17 JMP18 JMP19 JMP26 JMP27 JMP28 JMP29 JMP30 JMP31 JMP32 JMP33 JMP34 JMP35 JMP36 JMP37 JMP38 JMP39 JMP40 MH1 MH2 MH3 MH4 MH5 MH6 MH7 MOD1 R1 R4 R70 R95 R96 SB6 SB7 TP28 TP30 TP84 X2
component class CS-DOC-000013317[Connections]: C9 Fid1 Fid2 Fid3 S1 SB2 SB3
differential pair USB_NRF54: +nRF54_P -nRF54_N
differential pair USB_DBGR: +DBGR_P -DBGR_N
differential pair D: +D_P -D_N

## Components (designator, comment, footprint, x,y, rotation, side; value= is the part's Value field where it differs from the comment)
C1 "0201, 820pF, 25V" "Cap, C0201, Height 0.3mm" 26.63,10.508 r90 top value=820pF
C2 "0201, 100nF, 10V" "Cap, C0201, Height 0.3mm" 38.234,36.925 r270 top value=100nF
C3 "0603, 10uF, 10V" "Chip, 0603, RF" 133.16,32.706 r90 bottom value=10uF
C4 "0402, 2.2uF, 10V" "Chip. 0402, RF" 23.777,42.656 r180 top value=2.2uF
C5 "0603, 4.7µF, 10V" "Chip, 0603, RF" 24.007,46.586 r0 top value=4.7uF
C6 "0201, 1uF, 10V" "Cap, C0201, Height 0.3mm" 20.545,17.472 r90 top value=1uF
C7 "0201, 15pF, 50V" "Cap, C0201, Height 0.3mm" 23.872,37.305 r180 top value=15pF
C8 "0402, 2.2uF, 10V" "Chip. 0402, RF" 25.439,39.342 r90 top value=2.2uF
C9 "0201, 100nF, 10V" "Cap, C0201, Height 0.3mm" 71.458,44.065 r90 top value=100nF
C10 "0201, 100nF, 10V" "Cap, C0201, Height 0.3mm" 34.207,39.008 r0 top value=100nF
C11 "0402, 1.0uF 10V" "Chip. 0402, RF" 34.288,38.21 r0 top value=1.0uF
C13 "0201, 100nF, 10V" "Cap, C0201, Height 0.3mm" 17.545,15.574 r90 top value=100nF
C18 "0201, 100nF, 10V" "Cap, C0201, Height 0.3mm" 16.249,11.653 r180 top value=100nF
C20 "0201, 100nF, 10V" "Cap, C0201, Height 0.3mm" 18.219,7.599 r270 top value=100nF
C21 "0402, 10nF, 50V" "Chip. 0402, RF" 29.243,34.882 r180 top value=10nF
C23 "0201, 100nF, 10V" "Cap, C0201, Height 0.3mm" 31.343,37.699 r270 top value=100nF
C24 "0201, 100nF, 10V" "Cap, C0201, Height 0.3mm" 26.152,36.932 r0 top value=100nF
C25 "0201, 100nF, 10V" "Cap, C0201, Height 0.3mm" 46.728,46.133 r90 top value=100nF
C26 "0201, 100nF, 10V" "Cap, C0201, Height 0.3mm" 41.75,46.205 r270 top value=100nF
C27 "0201, 100nF, 10V" "Cap, C0201, Height 0.3mm" 46.564,36.632 r180 top value=100nF
C28 "0201, 100nF, 10V" "Cap, C0201, Height 0.3mm" 39.514,46.991 r180 top value=100nF
C29 "0603, 10uF, 10V" "Chip, 0603, RF" 134.08,30.187 r180 bottom value=10uF
C30 "0201, 100nF, 10V" "Cap, C0201, Height 0.3mm" 39.887,44.298 r90 top value=100nF
C31 "0201, 1uF, 10V" "Cap, C0201, Height 0.3mm" 23.52,18.349 r90 top value=1uF
C32 "0201, 1uF, 10V" "Cap, C0201, Height 0.3mm" 25.77,17.524 r180 top value=1uF
C33 "0201, 2200pF, 16V" "Cap, C0201, Height 0.3mm" 27.445,15.124 r90 top value=2200pF
C34 "0201, 100nF, 10V" "Cap, C0201, Height 0.3mm" 24.295,7.599 r270 top value=100nF
C35 "0201, 100nF, 10V" "Cap, C0201, Height 0.3mm" 27.053,12.866 r0 top value=100nF
C36 "0201, 100nF, 10V" "Cap, C0201, Height 0.3mm" 26.895,15.124 r270 top value=100nF
C37 "0201, 100nF, 10V" "Cap, C0201, Height 0.3mm" 27.141,16.963 r0 top value=100nF
C38 "0603, 1.0uF, 10V" "Chip, 0603, RF" 23.949,52.35 r180 top value=1.0uF
C39 "0201, 1uF, 10V" "Cap, C0201, Height 0.3mm" 21.843,18.429 r180 top value=1uF
C40 "0402, 2.2uF, 10V" "Chip. 0402, RF" 16.245,13.242 r90 top value=2.2uF
C41 "0201, 100nF, 10V" "Cap, C0201, Height 0.3mm" 19.312,27.202 r180 top value=100nF
C42 "0603, 4.7µF, 10V" "Chip, 0603, RF" 18.245,18.529 r90 top value=4.7µF
C43 "0603, 4.7µF, 10V" "Chip, 0603, RF" 19.37,18.529 r90 top value=4.7µF
C44 "0201, 100nF, 10V" "Cap, C0201, Height 0.3mm" 24.192,16.789 r0 top value=100nF
C45 "0201, 1uF, 10V" "Cap, C0201, Height 0.3mm" 21.445,17.579 r180 top value=1uF
C46 "0201, 100nF, 10V" "Cap, C0201, Height 0.3mm" 33.594,23.634 r0 top value=100nF
C47 "0201, 100nF, 10V" "Cap, C0201, Height 0.3mm" 33.528,8.484 r0 top value=100nF
C48 "0201, 100nF, 10V" "Cap, C0201, Height 0.3mm" 33.561,18.632 r0 top value=100nF
C49 "0201, 100nF, 10V" "Cap, C0201, Height 0.3mm" 33.583,13.631 r0 top value=100nF
C50 "0201, 100nF, 10V" "Cap, C0201, Height 0.3mm" 25.617,23.646 r90 top value=100nF
C51 "0201, 100nF, 10V" "Cap, C0201, Height 0.3mm" 30.613,22.717 r90 top value=100nF
C52 "0603, 1.0uF, 10V" "Chip, 0603, RF" 23.949,50.075 r0 top value=1.0uF
C53 "0201, 100nF, 10V" "Cap, C0201, Height 0.3mm" 21.297,7.599 r270 top value=100nF
C54 "0201, 100nF, 10V" "Cap, C0201, Height 0.3mm" 33.561,19.882 r0 top value=100nF
C55 "0201, 100nF, 10V" "Cap, C0201, Height 0.3mm" 33.583,14.881 r0 top value=100nF
C56 "0201, 100nF, 10V" "Cap, C0201, Height 0.3mm" 33.528,9.734 r0 top value=100nF
C57 "0201, 100nF, 10V" "Cap, C0201, Height 0.3mm" 33.594,24.884 r0 top value=100nF
C58 "0603, 10uF, 10V" "Chip, 0603, RF" 23.949,48.825 r180 top value=10uF
C59 "0201, 100nF, 10V" "Cap, C0201, Height 0.3mm" 29.363,22.717 r90 top value=100nF
C60 "0201, 100nF, 10V" "Cap, C0201, Height 0.3mm" 24.367,23.646 r90 top value=100nF
C61 "0603, 10uF, 10V" "Chip, 0603, RF" 14.149,51 r270 top value=10uF
C62 "0201, 100nF, 10V" "Cap, C0201, Height 0.3mm" 127.868,42.362 r90 bottom value=100nF
C63 "0201, 100nF, 10V" "Cap, C0201, Height 0.3mm" 125.524,38.034 r180 bottom value=100nF
C64 "0201, 100nF, 10V" "Cap, C0201, Height 0.3mm" 124.074,42.709 r0 bottom value=100nF
C65 "0402, 300pF, 50V" "Chip. 0402, RF" 133.793,57.942 r0 top value=300pF
C66 "0402, 300pF, 50V" "Chip. 0402, RF" 132.324,57.942 r180 top value=300pF
C67 "0603, 10uF, 10V" "Chip, 0603, RF" 14.149,48.4 r90 top value=10uF
C68 "0603, 4.7µF, 10V" "Chip, 0603, RF" 4.848,51.43 r270 top value=4.7uF
C69 "0603, 10uF, 10V" "Chip, 0603, RF" 14.824,53.1 r0 top value=10uF
C70 "0603, 10uF, 10V" "Chip, 0603, RF" 12.199,46.55 r180 top value=10uF
C71 "0201, 100nF, 10V" "Cap, C0201, Height 0.3mm" 17.89,45.448 r270 top value=100nF
C72 "0603, 10uF, 10V" "Chip, 0603, RF" 20.374,54.95 r270 top value=10uF
C73 "0402, 1.0uF 10V" "Chip. 0402, RF" 29.276,42.743 r90 top value=1.0uF
C74 "0402, 1.0uF 10V" "Chip. 0402, RF" 27.809,39.697 r0 top value=1.0uF
C75 "0402, 4.7uF, 6.3V" "Chip. 0402, RF" 128.941,42.127 r0 bottom value=4.7uF
C76 "0402, 4.7uF, 6.3V" "Chip. 0402, RF" 123.673,43.756 r90 bottom value=4.7uF
C77 "0201, 100nF, 10V" "Cap, C0201, Height 0.3mm" 24.235,47.993 r180 top value=100nF
C79 "0402, 1.0uF 10V" "Chip. 0402, RF" 31.301,46.143 r270 top value=1.0uF
C80 "0402, 1.0uF 10V" "Chip. 0402, RF" 36.26,45.349 r90 top value=1.0uF
C84 "0402, 1.0uF 10V" "Chip. 0402, RF" 31.246,41.585 r90 top value=1.0uF
C85 "0402, 1.0uF 10V" "Chip. 0402, RF" 36.244,42.457 r270 top value=1.0uF
C87 "0201, 100nF, 10V" "Cap, C0201, Height 0.3mm" 13.668,39.847 r270 top value=100nF
C88 "0201, 10nF, 10V" "Cap, C0201, Height 0.3mm" 11.499,40.476 r270 top value=10nF
C89 "0201, 10nF, 10V" "Cap, C0201, Height 0.3mm" 11.536,27.521 r270 top value=10nF
C90 "0201, 100nF, 10V" "Cap, C0201, Height 0.3mm" 13.704,27.422 r90 top value=100nF
C96 "0603, 10uF, 10V" "Chip, 0603, RF" 19.174,54.95 r270 top value=10uF
C98 "0603, 10uF, 10V" "Chip, 0603, RF" 17.974,54.95 r270 top value=10uF
C99 "0603, 10uF, 10V" "Chip, 0603, RF" 16.744,54.975 r270 top value=10uF
D1 "Panjit, PJDLC05_R1_10001" SOT-23 13.024,36.669 r0 top value=PJDLC05_R1_10001
D2 "Panjit, PJDLC05_R1_10001" SOT-23 13.024,23.86 r0 top value=PJDLC05_R1_10001
FB1 "Murata, BLM15AG121SN1" "FB, FB0402, RF" 12.593,40.11 r0 top value=BLM15AG121SN1
FB2 "Murata, BLM15AG121SN1" "FB, FB0402, RF" 12.627,27.16 r0 top value=BLM15AG121SN1
Fid1 "Fiducial" Fiducial 3.188,4.568 r0 top
Fid2 "Fiducial" Fiducial 137.009,8.518 r0 top
Fid3 "Fiducial" Fiducial 126.557,62.057 r0 top
J1 "Kingmate, S110-S-02-2-60/25/30" "2P54MM-1X2, male" 133.083,53.635 r180 top value=S110-S-02-2-60/25/30
J2 "Kingconn, 7USB31-F0-0029" "Kingconn, 7USB31-F0-0029" 6.37,37.547 r270 top value=7USB31-F0-0029
J3 "Kingconn, 7USB31-F0-0029" "Kingconn, 7USB31-F0-0029" 6.37,24.768 r270 top locked value=7USB31-F0-0029
J4 "Tag-Connect, TC2050-IDC-xx" "TC2050-NL, TAG Test Interface" 24.403,2.519 r0 top value=TC2050-IDC-NL
J7 "Molex, 0512810598" "Molex, 0512810598" 133.048,61.26 r270 top value=0512810598
J45 "Kingmate, S113-A-03-2-60/33-F0" "2P54MM-1X3, male" 106.078,46.624 r270 top locked value=S113-A-03-2-60/33-F0
J58 "Kingmate, S123-T-26-2-60/33-F0" 2P54MM-2X13Male 118.938,6.007 r180 top locked value=S123-T-26-2-60/33-F0
J59 "WCON, WF1001-WM04ER1" "CON WAFER, 1X4P" 56.365,52.861 r0 top value=WF1001-WM04ER1
J60 "WCON, 2185-108MG0CYNR2" "2P54MM-1X8, Female" 36.606,29.952 r0 top locked value=2185-108MG0CYNR2
J61 "WCON, 2185-108MG0CYNR2" "2P54MM-1X8, Female" 36.606,52.812 r0 top locked value=2185-108MG0CYNR2
J69 "Kingmate, S123-T-26-2-60/33-F0" 2P54MM-2X13Male 79.017,18.284 r270 top locked value=S123-T-26-2-60/33-F0
J70 "Kingmate, S123-T-22-2-60/33-F0" "2P54MM-2X11 Male" 92.281,40.661 r270 top locked value=S123-T-22-2-60/33-F0
J71 "Kingmate, S123-T-18-2-60/33-F0" "2P54MM-2X9 Male" 92.281,13.204 r270 top locked value=S123-T-18-2-60/33-F0
J72 "Kingmate, S123-T-14-2-60/33-F0" "2P54MM-2X7 Male" 105.92,21.984 r270 top locked value=S123-T-14-2-60/33-F0
J73 "Kingmate, S123-T-08-2-60/33-F0" "2P54MM-2X4 Male" 105.92,37.189 r270 top locked
JMP1 "Kingmate, S901D-1-1-E1" "Sullins, QPC02SXGN-RC" 79.018,30.983 r0 top value="Jumper CAP open type, Pitch 2.54mm"
JMP2 "Kingmate, S901D-1-1-E1" "Sullins, QPC02SXGN-RC" 79.018,28.443 r180 top value="Jumper CAP open type, Pitch 2.54mm"
JMP3 "Kingmate, S901D-1-1-E1" "Sullins, QPC02SXGN-RC" 79.018,25.903 r0 top value="Jumper CAP open type, Pitch 2.54mm"
JMP4 "Kingmate, S901D-1-1-E1" "Sullins, QPC02SXGN-RC" 79.018,23.363 r180 top value="Jumper CAP open type, Pitch 2.54mm"
JMP5 "Kingmate, S901D-1-1-E1" "Sullins, QPC02SXGN-RC" 129.098,6.006 r270 top locked value="Jumper CAP open type, Pitch 2.54mm"
JMP6 "Kingmate, S901D-1-1-E1" "Sullins, QPC02SXGN-RC" 126.558,6.006 r90 top locked value="Jumper CAP open type, Pitch 2.54mm"
JMP7 "Kingmate, S901D-1-1-E1" "Sullins, QPC02SXGN-RC" 124.018,6.006 r270 top locked value="Jumper CAP open type, Pitch 2.54mm"
JMP8 "Kingmate, S901D-1-1-E1" "Sullins, QPC02SXGN-RC" 121.478,6.006 r270 top locked value="Jumper CAP open type, Pitch 2.54mm"
JMP9 "Kingmate, S901D-1-1-E1" "Sullins, QPC02SXGN-RC" 111.318,6.006 r90 top locked value="Jumper CAP open type, Pitch 2.54mm"
JMP10 "Kingmate, S901D-1-1-E1" "Sullins, QPC02SXGN-RC" 108.778,6.006 r90 top locked value="Jumper CAP open type, Pitch 2.54mm"
JMP11 "Kingmate, S901D-1-1-E1" "Sullins, QPC02SXGN-RC" 106.238,6.006 r90 top locked value="Jumper CAP open type, Pitch 2.54mm"
JMP12 "Kingmate, S901D-1-1-E1" "Sullins, QPC02SXGN-RC" 103.699,6.007 r90 top locked value="Jumper CAP open type, Pitch 2.54mm"
JMP13 "Kingmate, S901D-1-1-E1" "Sullins, QPC02SXGN-RC" 92.281,43.201 r180 top locked value="Jumper CAP open type, Pitch 2.54mm"
JMP14 "Kingmate, S901D-1-1-E1" "Sullins, QPC02SXGN-RC" 92.281,40.661 r180 top locked value="Jumper CAP open type, Pitch 2.54mm"
JMP15 "Kingmate, S901D-1-1-E1" "Sullins, QPC02SXGN-RC" 92.281,38.121 r180 top locked value="Jumper CAP open type, Pitch 2.54mm"
JMP16 "Kingmate, S901D-1-1-E1" "Sullins, QPC02SXGN-RC" 92.281,35.581 r180 top locked value="Jumper CAP open type, Pitch 2.54mm"
JMP17 "Kingmate, S901D-1-1-E1" "Sullins, QPC02SXGN-RC" 92.281,33.041 r180 top locked value="Jumper CAP open type, Pitch 2.54mm"
JMP18 "Kingmate, S901D-1-1-E1" "Sullins, QPC02SXGN-RC" 92.281,30.501 r180 top locked value="Jumper CAP open type, Pitch 2.54mm"
JMP19 "Kingmate, S901D-1-1-E1" "Sullins, QPC02SXGN-RC" 92.281,27.961 r180 top locked value="Jumper CAP open type, Pitch 2.54mm"
JMP20 "Kingmate, S901D-1-1-E1" "Sullins, QPC02SXGN-RC" 19.984,60.055 r180 top locked value="Jumper CAP open type, Pitch 2.54mm"
JMP21 "Kingmate, S901D-1-1-E1" "Sullins, QPC02SXGN-RC" 62.553,60.055 r180 top locked value="Jumper CAP open type, Pitch 2.54mm"
JMP22 "Kingmate, S901D-1-1-E1" "Sullins, QPC02SXGN-RC" 70.867,60.055 r180 top locked value="Jumper CAP open type, Pitch 2.54mm"
JMP23 "Kingmate, S901D-1-1-E1" "Sullins, QPC02SXGN-RC" 52.875,3.334 r180 top value="Jumper CAP open type, Pitch 2.54mm"
JMP24 "Kingmate, S901D-1-1-E1" "Sullins, QPC02SXGN-RC" 79.226,60.055 r180 top locked value="Jumper CAP open type, Pitch 2.54mm"
JMP25 "Kingmate, S901D-1-1-E1" "Sullins, QPC02SXGN-RC" 87.54,60.055 r180 top locked value="Jumper CAP open type, Pitch 2.54mm"
JMP26 "Kingmate, S901D-1-1-E1" "Sullins, QPC02SXGN-RC" 92.281,23.364 r180 top locked value="Jumper CAP open type, Pitch 2.54mm"
JMP27 "Kingmate, S901D-1-1-E1" "Sullins, QPC02SXGN-RC" 92.281,20.824 r180 top locked value="Jumper CAP open type, Pitch 2.54mm"
JMP28 "Kingmate, S901D-1-1-E1" "Sullins, QPC02SXGN-RC" 92.281,18.284 r180 top locked value="Jumper CAP open type, Pitch 2.54mm"
JMP29 "Kingmate, S901D-1-1-E1" "Sullins, QPC02SXGN-RC" 92.281,15.744 r180 top locked value="Jumper CAP open type, Pitch 2.54mm"
JMP30 "Kingmate, S901D-1-1-E1" "Sullins, QPC02SXGN-RC" 92.281,13.204 r180 top locked value="Jumper CAP open type, Pitch 2.54mm"
JMP31 "Kingmate, S901D-1-1-E1" "Sullins, QPC02SXGN-RC" 92.281,10.664 r180 top locked value="Jumper CAP open type, Pitch 2.54mm"
JMP32 "Kingmate, S901D-1-1-E1" "Sullins, QPC02SXGN-RC" 92.281,8.124 r180 top locked value="Jumper CAP open type, Pitch 2.54mm"
JMP33 "Kingmate, S901D-1-1-E1" "Sullins, QPC02SXGN-RC" 92.281,5.584 r180 top locked value="Jumper CAP open type, Pitch 2.54mm"
JMP34 "Kingmate, S901D-1-1-E1" "Sullins, QPC02SXGN-RC" 105.92,24.524 r180 top locked value="Jumper CAP open type, Pitch 2.54mm"
JMP35 "Kingmate, S901D-1-1-E1" "Sullins, QPC02SXGN-RC" 105.92,21.984 r0 top locked value="Jumper CAP open type, Pitch 2.54mm"
JMP36 "Kingmate, S901D-1-1-E1" "Sullins, QPC02SXGN-RC" 105.92,19.444 r0 top locked value="Jumper CAP open type, Pitch 2.54mm"
JMP37 "Kingmate, S901D-1-1-E1" "Sullins, QPC02SXGN-RC" 105.92,16.904 r0 top locked value="Jumper CAP open type, Pitch 2.54mm"
JMP38 "Kingmate, S901D-1-1-E1" "Sullins, QPC02SXGN-RC" 105.92,40.999 r180 top locked value="Jumper CAP open type, Pitch 2.54mm"
JMP39 "Kingmate, S901D-1-1-E1" "Sullins, QPC02SXGN-RC" 105.92,38.459 r180 top locked value="Jumper CAP open type, Pitch 2.54mm"
JMP40 "Kingmate, S901D-1-1-E1" "Sullins, QPC02SXGN-RC" 105.92,35.919 r180 top locked value="Jumper CAP open type, Pitch 2.54mm"
L7 "0806, 2.2uH, 1.6A" "IND, 0806, Height 1.0mm" 12.274,51.475 r270 top value=2.2uH
L10 "0806, 2.2uH, 1.6A" "IND, 0806, Height 1.0mm" 12.044,48.751 r0 top value=2.2uH
LED1 "Everlight, 19-217/B7C-ZL2N1B3X/3T" "Everlight, LED0603, Blue" 29.671,6.539 r270 top value=Blue
LED2 "Everlight, 19-217/B7C-ZL2N1B3X/3T" "Everlight, LED0603, Blue" 65.322,13.397 r0 top value=Blue
LED3 "Everlight, 19-217/B7C-ZL2N1B3X/3T" "Everlight, LED0603, Blue" 60.432,15.633 r0 top value=Blue
LED4 "Everlight, 19-217/B7C-ZL2N1B3X/3T" "Everlight, LED0603, Blue" 60.432,13.397 r0 top value=Blue
LED5 "Everlight, 19-217/B7C-ZL2N1B3X/3T" "Everlight, LED0603, Blue" 65.322,15.597 r0 top value=Blue
LOGO_MICRO_BUS1 "Comment" LOGO_MICROBUS_GTO_W12.24 51.489,35.18 r90 top
LOGO_QWIIC "Comment" LOGO_QWIIC_GTO_W7.0 51.963,49.355 r90 top
MH1 "Mounting Hole, Hole 3.2mm, Dia 6mm" "Screw Hole, Hole 3.2mm, Dia 6mm" 117.359,46.75 r0 top
MH2 "Mounting Hole, Hole 3.2mm, Dia 6mm" "Screw Hole, Hole 3.2mm, Dia 6mm" 152.359,46.75 r180 top locked
MH3 "Mounting Hole, Hole 3.2mm, Dia 6mm" "Screw Hole, Hole 3.2mm, Dia 6mm" 152.359,16.75 r180 top locked
MH4 "Mounting Hole, Hole 3.2mm, Dia 6mm" "Screw Hole, Hole 3.2mm, Dia 6mm" 117.359,16.75 r0 top locked
MH5 "Mounting Hole, Hole 1.524mm, Dia 1.524mm" "Screw Hole, Hole 1.524mm, Dia 1.524mm" 147.359,41.75 r0 top
MH6 "Mounting Hole, Hole 1.524mm, Dia 1.524mm" "Screw Hole, Hole 1.524mm, Dia 1.524mm" 147.359,21.75 r270 top locked
MH7 "Mounting Hole, Hole 1.524mm, Dia 1.524mm" "Screw Hole, Hole 1.524mm, Dia 1.524mm" 122.359,21.75 r180 top
MOD1 "Ezurio, 453-00197, Platform Side" "Laird, BL54H20 Module, Chip Antenna, Platform Side" 134.759,31.75 r0 top locked value="BL54H20, Chip Antenna"
P1 "Molex,  0530480310" "Molex, 0530480310" 32.471,59.087 r180 top value=0530480310
P2 "Kingmate, S113-A-03-2-60/33-F0" "2P54MM-1X3, male" 54.716,60.055 r180 top value=S113-A-03-2-60/33-F0
P15 "Kingmate, N123-1-10-2-30/20/25/G1" "1P27MM-2X5 Male"#1 115.716,58.716 r0 top locked value=N123-1-10-2-30/20/25/G1
P16 "Kingmate, N123-1-20-2-30/20/25" "1P27MM-2X10 Male" 118.891,58.716 r90 top locked value=N123-1-20-2-30/20/25
P19 "Kingmate, N123-1-10-2-30/20/25/G1" "1P27MM-2X5 Male"#2 14.412,3.76 r0 top value=N123-1-10-2-30/20/25/G1
P20 "Kingmate, S113-A-03-2-60/33-F0" "2P54MM-1X3, male" 21.254,60.055 r180 top value=S113-A-03-2-60/33-F0
P21 "Kingmate, S113-A-03-2-60/33-F0" "2P54MM-1X3, male" 63.823,60.055 r180 top value=S113-A-03-2-60/33-F0
P22 "Kingmate, S113-A-03-2-60/33-F0" "2P54MM-1X3, male" 72.137,60.055 r180 top locked value=S113-A-03-2-60/33-F0
P23 "Kingmate, S113-A-03-2-60/33-F0" "2P54MM-1X3, male" 54.145,3.334 r180 top locked value=S113-A-03-2-60/33-F0
P24 "Kingmate, S113-A-03-2-60/33-F0" "2P54MM-1X3, male" 80.496,60.055 r180 top value=S113-A-03-2-60/33-F0
P25 "Kingmate, S113-A-03-2-60/33-F0" "2P54MM-1X3, male" 88.81,60.055 r180 top value=S113-A-03-2-60/33-F0
P29 "Kingmate, S113-A-03-2-60/33-F0" "2P54MM-1X3, male" 107.752,60.055 r180 top value=S113-A-03-2-60/33-F0
P42 "Kingmate, S113-A-03-2-60/33-F0" "2P54MM-1X3, male" 36.076,3.334 r180 top value=S113-A-03-2-60/33-F0
P45 "Kingmate, S113-B-04-2-58/38-F0" "2P54MM-1X4, male" 98.212,60.055 r180 top value=S113-B-04-2-58/38-F0
Q1 "Rohm, RV2C010UNT2L" DFN1006-3 28.164,5.825 r0 top value=RV2C010UNT2L
Q2 "Rohm, RV2C010UNT2L" DFN1006-3 70.236,12.836 r180 top value=RV2C010UNT2L
Q3 "Rohm, RV2C010UNT2L" DFN1006-3 70.236,15.017 r180 top value=RV2C010UNT2L
Q4 "MCC, MCM2301-TP" "MCC, MCM2301-TP" 6.624,50.257 r90 top value=MCM2301-TP
Q5 "MCC, MCM2301-TP" "MCC, MCM2301-TP" 3.075,50.258 r90 top value=MCM2301-TP
Q6 "Rohm, RV2C010UNT2L" DFN1006-3 23.971,20.717 r0 top value=RV2C010UNT2L
Q7 "Rohm, RV2C010UNT2L" DFN1006-3 52.422,39.226 r180 top value=RV2C010UNT2L
Q9 "Rohm, RV2C010UNT2L" DFN1006-3 70.236,13.926 r180 top value=RV2C010UNT2L
Q10 "Rohm, RV2C010UNT2L" DFN1006-3 70.236,16.108 r180 top value=RV2C010UNT2L
R1 "0201, 2.2, 1%" "RES, R0201, Height 0.23mm" 132.949,31.035 r0 bottom value=2.2
R2 "0201, 47k, 1%" "RES, R0201, Height 0.23mm" 21.578,45.45 r270 top value=47k
R3 "0201, 4.7k, 1%" "RES, R0201, Height 0.23mm" 57.865,49.401 r270 top value=4.7k
R4 "0201, 0 Ohm" "RES, R0201, Height 0.23mm" 132.754,55.606 r270 bottom value=0
R5 "0201, 1.0k, 5%" "RES, R0201, Height 0.23mm" 29.611,8.543 r90 top value=1.0k
R6 "0201, 100k, 1%" "RES, R0201, Height 0.23mm" 22.12,5.438 r0 top value=100k
R7 "0201, 49.9 Ohm, 1%" "RES, R0201, Height 0.23mm" 27.045,13.474 r0 top value=49.9
R8 "0201, 100k, 1%" "RES, R0201, Height 0.23mm" 33.536,7.677 r180 top value=100k
R9 "0201, 100k, 1%" "RES, R0201, Height 0.23mm" 33.583,12.656 r180 top value=100k
R10 "0201, 4.7k, 1%" "RES, R0201, Height 0.23mm" 56.831,49.401 r270 top value=4.7k
R11 "0201, 2.2, 1%" "RES, R0201, Height 0.23mm" 18.07,16.999 r0 top value=2.2
R12 "0201, 10k, 1%" "RES, R0201, Height 0.23mm" 47.407,13.505 r0 top value=10k
R13 "0201, 10k, 1%" "RES, R0201, Height 0.23mm" 47.018,20.226 r0 top value=10k
R14 "0201, 10k, 1%" "RES, R0201, Height 0.23mm" 54.215,41.355 r180 top value=10k
R15 "0201, 100k, 1%" "RES, R0201, Height 0.23mm" 36.728,24.211 r180 top value=100k
R16 "0201, 100k, 1%" "RES, R0201, Height 0.23mm" 36.744,8.962 r180 top value=100k
R17 "0201, 100k, 1%" "RES, R0201, Height 0.23mm" 36.713,18.987 r180 top value=100k
R18 "0201, 100k, 1%" "RES, R0201, Height 0.23mm" 36.738,14.04 r180 top value=100k
R19 "0201, 100k, 1%" "RES, R0201, Height 0.23mm" 25.336,20.743 r0 top value=100k
R20 "0201, 1.2k, 5%" "RES, R0201, Height 0.23mm" 63.291,13.403 r180 top value=1.2k
R21 "0201, 1.2k, 5%" "RES, R0201, Height 0.23mm" 58.401,15.597 r180 top value=1.2k
R22 "0201, 100k, 1%" "RES, R0201, Height 0.23mm" 13.635,15.772 r180 top value=100k
R23 "0201, 100k, 1%" "RES, R0201, Height 0.23mm" 121.901,42.375 r270 bottom value=100k
R24 "0201, 0 Ohm" "RES, R0201, Height 0.23mm" 133.355,56.959 r270 top value=0
R25 "0201, 0 Ohm" "RES, R0201, Height 0.23mm" 132.791,56.959 r270 top value=0
R26 "0201, 10k, 1%" "RES, R0201, Height 0.23mm" 6.766,47.612 r0 top value=10k
R27 "0201, 100k, 1%" "RES, R0201, Height 0.23mm" 1.7,52.016 r180 top value=100k
R28 "0201, 0 Ohm" "RES, R0201, Height 0.23mm" 123.563,40.785 r0 bottom value=0
R29 "0201, 270k, 1%" "RES, R0201, Height 0.23mm" 20.934,45.451 r270 top value=270k
R30 "0402, 10, 5%" "RES, R0402, RF" 105.699,59.28 r0 bottom value=10
R31 "0402, 10, 5%" "RES, R0402, RF" 95.949,61.319 r270 bottom value=10
R32 "0201, 1M, 1%" "RES, R0201, Height 0.23mm" 1.973,48.518 r180 top value=1M
R33 "0402, 18.2k, 1%" "RES, R0402, RF" 27.773,34.022 r180 top value=18.2k
R34 "0402, 10, 5%" "RES, R0402, RF" 61.679,58.35 r0 bottom value=10
R35 "0402, 10, 5%" "RES, R0402, RF" 69.462,55.126 r270 top value=10
R36 "0201, 100k, 1%" "RES, R0201, Height 0.23mm" 51.1,39.226 r0 top value=100k
R37 "0402, 10, 5%" "RES, R0402, RF" 52.757,8.457 r270 top value=10
R38 "0201, 10k, 1%" "RES, R0201, Height 0.23mm" 46.989,26.421 r0 top value=10k
R39 "0402, 10, 5%" "RES, R0402, RF" 78.334,59.026 r0 bottom value=10
R40 "0201, 100k, 1%" "RES, R0201, Height 0.23mm" 20.428,27.198 r0 top value=100k
R41 "0402, 10, 5%" "RES, R0402, RF" 86.699,58.48 r0 bottom value=10
R42 "0201, 1M, 1%" "RES, R0201, Height 0.23mm" 5.596,48.276 r180 top value=1M
R43 "0201, 0 Ohm" "RES, R0201, Height 0.23mm" 13.388,33.487 r90 top value=0
R44 "0201, 0 Ohm" "RES, R0201, Height 0.23mm" 12.73,33.487 r90 top value=0
R45 "0201, 5.1k, 1%" "RES, R0201, Height 0.23mm" 6.56,32.092 r90 top value=5.1k
R46 "0201, 5.1k, 1%" "RES, R0201, Height 0.23mm" 6.357,19.28 r90 top value=5.1k
R47 "0201, 5.1k, 1%" "RES, R0201, Height 0.23mm" 11.781,26.436 r0 top value=5.1k
R48 "0402, 18.2k, 1%" "RES, R0402, RF" 29.227,34.011 r180 top value=18.2k
R49 "0201, 5.1k, 1%" "RES, R0201, Height 0.23mm" 11.769,39.39 r180 top value=5.1k
R50 "0201, 0 Ohm" "RES, R0201, Height 0.23mm" 36.728,24.876 r180 top value=0
R51 "0402, 10, 5%" "RES, R0402, RF" 20.377,60.209 r0 bottom value=10
R52 "0201, 0 Ohm" "RES, R0201, Height 0.23mm" 35.49,24.278 r270 bottom value=0
R53 "0201, 0 Ohm" "RES, R0201, Height 0.23mm" 34.842,24.285 r270 bottom value=0
R54 "0201, 0 Ohm" "RES, R0201, Height 0.23mm" 35.45,9.227 r270 bottom value=0
R55 "0201, 0 Ohm" "RES, R0201, Height 0.23mm" 34.809,9.227 r270 bottom value=0
R56 "0201, 0 Ohm" "RES, R0201, Height 0.23mm" 35.466,19.277 r270 bottom value=0
R57 "0201, 0 Ohm" "RES, R0201, Height 0.23mm" 34.827,19.277 r270 bottom value=0
R58 "0201, 0 Ohm" "RES, R0201, Height 0.23mm" 35.471,14.205 r270 bottom value=0
R59 "0201, 0 Ohm" "RES, R0201, Height 0.23mm" 34.817,14.209 r270 bottom value=0
R60 "0201, 0 Ohm" "RES, R0201, Height 0.23mm" 29.995,23.984 r0 bottom value=0
R61 "0201, 0 Ohm" "RES, R0201, Height 0.23mm" 29.995,24.543 r0 bottom value=0
R62 "0201, 0 Ohm" "RES, R0201, Height 0.23mm" 24.995,24.892 r0 bottom value=0
R63 "0201, 0 Ohm" "RES, R0201, Height 0.23mm" 24.995,25.451 r0 bottom value=0
R64 "0201, 10k, 1%" "RES, R0201, Height 0.23mm" 1.969,47.878 r0 top value=10k
R65 "0201, 0 Ohm" "RES, R0201, Height 0.23mm" 36.742,9.608 r180 top value=0
R66 "0201, 0 Ohm" "RES, R0201, Height 0.23mm" 36.713,19.641 r180 top value=0
R67 "0201, 0 Ohm" "RES, R0201, Height 0.23mm" 36.742,14.69 r180 top value=0
R68 "0201, 1.2k, 5%" "RES, R0201, Height 0.23mm" 58.401,13.403 r180 top value=1.2k
R69 "0201, 1.2k, 5%" "RES, R0201, Height 0.23mm" 63.272,15.564 r180 top value=1.2k
R70 "0201, 0 Ohm" "RES, R0201, Height 0.23mm" 133.4,55.606 r270 bottom value=0
R71 "0201, 1M, 1%" "RES, R0201, Height 0.23mm" 71.26,12.896 r90 top value=1M
R72 "0201, 1M, 1%" "RES, R0201, Height 0.23mm" 71.26,15.077 r90 top value=1M
R73 "0201, 1M, 1%" "RES, R0201, Height 0.23mm" 71.26,13.986 r90 top value=1M
R74 "0201, 1M, 1%" "RES, R0201, Height 0.23mm" 71.26,16.168 r90 top value=1M
R75 "0201, 10k, 1%" "RES, R0201, Height 0.23mm" 28.321,35.648 r180 top value=10k
R76 "0201, 10k, 1%" "RES, R0201, Height 0.23mm" 43.817,44.501 r180 top value=10k
R77 "0201, 10k, 1%" "RES, R0201, Height 0.23mm" 40.421,41.735 r0 top value=10k
R78 "0201, 10k, 1%" "RES, R0201, Height 0.23mm" 39.013,44.528 r180 top value=10k
R79 "0201, 1M, 1%" "RES, R0201, Height 0.23mm" 26.98,45.488 r270 top value=1M
R80 "0201, 100k, 1%" "RES, R0201, Height 0.23mm" 29.414,35.648 r0 top value=100k
R81 "0201, 0 Ohm" "RES, R0201, Height 0.23mm" 22.239,20.672 r90 top value=0
R82 "0201, 100k, 1%" "RES, R0201, Height 0.23mm" 22.895,20.665 r90 top value=100k
R83 "0201, 0 Ohm" "RES, R0201, Height 0.23mm" 21.091,24.96 r180 top value=0
R84 "0201, 0 Ohm" "RES, R0201, Height 0.23mm" 25.686,45.483 r90 top value=0
R85 "0201, 0 Ohm" "RES, R0201, Height 0.23mm" 52.52,38.314 r0 top value=0
R86 "0201, 100k, 1%" "RES, R0201, Height 0.23mm" 52.818,37.435 r270 top value=100k
R87 "0201, 100k, 1%" "RES, R0201, Height 0.23mm" 34.85,34.773 r180 top value=100k
R88 "0201, 0 Ohm" "RES, R0201, Height 0.23mm" 50.009,59.019 r270 top value=0
R89 "0201, 100k, 1%" "RES, R0201, Height 0.23mm" 26.32,45.488 r90 top value=100k
R90 "0201, 31.6k, 1%" "RES, R0201, Height 0.23mm" 23.876,37.952 r180 top value=31.6k
R91 "0201, 10k, 1%" "RES, R0201, Height 0.23mm" 22.111,37.94 r180 top value=10k
R92 "0201, 100k, 1%" "RES, R0201, Height 0.23mm" 44.912,44.502 r0 top value=100k
R93 "0201, 100k, 1%" "RES, R0201, Height 0.23mm" 39.301,41.735 r180 top value=100k
R94 "0201, 100k, 1%" "RES, R0201, Height 0.23mm" 39.019,43.898 r180 top value=100k
R95 "0201, 0 Ohm" "RES, R0201, Height 0.23mm" 130.026,44.158 r270 top value=0
R96 "0201, 0 Ohm" "RES, R0201, Height 0.23mm" 128.689,45.113 r270 top value=0
R97 "0201, 0 Ohm" "RES, R0201, Height 0.23mm" 68.709,55.309 r90 top value=0
R98 "0201, 0 Ohm" "RES, R0201, Height 0.23mm" 53.524,8.562 r90 top value=0
R99 "0201, 0 Ohm" "RES, R0201, Height 0.23mm" 20.266,45.455 r90 top value=0
R100 "0201, 0 Ohm" "RES, R0201, Height 0.23mm" 18.491,45.447 r90 top value=0
R101 "0201, 0 Ohm" "RES, R0201, Height 0.23mm" 68.048,55.319 r270 top value=0
R102 "0201, 0 Ohm" "RES, R0201, Height 0.23mm" 53.749,9.431 r0 top value=0
R103 "0201, 0 Ohm" "RES, R0201, Height 0.23mm" 17.254,45.448 r90 top value=0
R104 "0201, 0 Ohm" "RES, R0201, Height 0.23mm" 11.293,53.262 r180 top value=0
R105 "0201, 0 Ohm" "RES, R0201, Height 0.23mm" 49.988,57.342 r90 top value=0
R106 "0201, 10k, 1%" "RES, R0201, Height 0.23mm" 19.061,45.449 r270 top value=10k
R107 "0201, 10k, 1%" "RES, R0201, Height 0.23mm" 19.642,45.447 r90 top value=10k
R108 "0201, 100k, 1%" "RES, R0201, Height 0.23mm" 22.591,21.582 r180 top value=100k
R109 "0201, 0 Ohm" "RES, R0201, Height 0.23mm" 44.486,13.485 r180 top value=0
R110 "0201, 0 Ohm" "RES, R0201, Height 0.23mm" 45.576,13.485 r0 top value=0
R111 "0201, 0 Ohm" "RES, R0201, Height 0.23mm" 44.347,20.226 r180 top value=0
R112 "0201, 0 Ohm" "RES, R0201, Height 0.23mm" 45.438,20.226 r0 top value=0
R113 "0201, 0 Ohm" "RES, R0201, Height 0.23mm" 54.447,39.808 r270 top value=0
R114 "0201, 0 Ohm" "RES, R0201, Height 0.23mm" 120.277,62.4 r0 top value=0
R115 "0201, 0 Ohm" "RES, R0201, Height 0.23mm" 121.871,62.4 r0 top value=0
R116 "0201, 100k, 1%" "RES, R0201, Height 0.23mm" 52.162,37.438 r90 top value=100k
R117 "0201, 10k, 1%" "RES, R0201, Height 0.23mm" 54.254,37.973 r180 top value=10k
R118 "0201, 10k, 1%" "RES, R0201, Height 0.23mm" 54.215,40.71 r180 top value=10k
R119 "0201, 10k, 1%" "RES, R0201, Height 0.23mm" 54.258,37.319 r180 top value=10k
R120 "0201, 0 Ohm" "RES, R0201, Height 0.23mm" 15.28,46.543 r90 top value=0
R121 "0201, 0 Ohm" "RES, R0201, Height 0.23mm" 31.815,35.751 r90 top value=0
R122 "0201, 0 Ohm" "RES, R0201, Height 0.23mm" 31.576,36.609 r180 top value=0
R123 "0201, 0 Ohm" "RES, R0201, Height 0.23mm" 123.414,62.4 r0 top value=0
S1 "Touke, TS-06M-ASM-T-T/R" "Touke, TS-06M-ASM-T" 66.212,46.064 r0 top locked value=TS-06M-ASM-T-T/R
SB1 "Solderbridge Open" "Solder Bridge Open" 12.238,15.773 r0 top
SB2 "Solderbridge Closed" "Solder Bridge Closed" 12.263,11.889 r0 top net-tie
SB3 "Solderbridge Open" "Solder Bridge Open" 12.238,13.831 r0 top
SB4 "Solderbridge Closed" "Solder Bridge Closed" 104.868,56.519 r180 bottom net-tie
SB5 "Solderbridge Open" "Solder Bridge Open" 104.91,57.863 r180 bottom
SB6 "Solderbridge Closed" "Solder Bridge Closed" 126.918,28.953 r0 top net-tie
SB7 "Solderbridge Closed" "Solder Bridge Closed" 126.918,30.394 r0 top net-tie
SW1 "Touke, TS-06M-ASM-T-T/R" "Touke, TS-06M-ASM-T" 6.091,11.337 r180 top value=TS-06M-ASM-T-T/R
SW2 "Touke, TS-06M-ASM-T-T/R" "Touke, TS-06M-ASM-T" 79.254,40.937 r0 top locked value=TS-06M-ASM-T-T/R
SW3 "Touke, TS-06M-ASM-T-T/R" "Touke, TS-06M-ASM-T" 66.212,26.565 r180 top locked value=TS-06M-ASM-T-T/R
SW4 "C&K, JS202011SCQN" "C&K, JS202011SCQN" 5.322,58.169 r270 top value=JS202011SCQN
SW5 "Touke, TS-06M-ASM-T-T/R" "Touke, TS-06M-ASM-T" 66.212,36.726 r0 top locked value=TS-06M-ASM-T-T/R
SW6 "Touke, TS-06M-ASM-T-T/R" "Touke, TS-06M-ASM-T" 79.254,50.187 r0 top locked value=TS-06M-ASM-T-T/R
SW7 "Contact, SS-B95A-W-S246" "Contact, SS-B95A-W-S246" 44.453,23.337 r0 top locked value=SS-B95A-W-S246
SW8 "Contact, SS-B95A-W-S246" "Contact, SS-B95A-W-S246" 44.453,10.361 r0 top locked value=SS-B95A-W-S246
SW9 "Contact, SS-B95A-W-S246" "Contact, SS-B95A-W-S246" 44.453,16.841 r0 top locked value=SS-B95A-W-S246
SW10 "Contact, SS-B95A-W-S246" "Contact, SS-B95A-W-S246" 57.569,39.491 r90 top locked value=SS-B95A-W-S246
TP1 "SMT, 1.5mm, Test Pad" "Test Point, SMT 1.5mm Round" 29.611,4.115 r180 bottom
TP2 "SMT, 1.5mm, Test Pad" "Test Point, SMT 1.5mm Round" 23.611,4.115 r180 bottom
TP3 "SMT, 1.5mm, Test Pad" "Test Point, SMT 1.5mm Round" 20.611,4.115 r180 bottom
TP4 "SMT, 1.5mm, Test Pad" "Test Point, SMT 1.5mm Round" 26.611,4.115 r180 bottom
TP5 "SMT, 1.5mm, Test Pad" "Test Point, SMT 1.5mm Round" 37.411,38.712 r180 bottom
TP7 "SMT, 1.5mm, Test Pad" "Test Point, SMT 1.5mm Round" 26.87,54.915 r270 bottom
TP8 "SMT, 1.5mm, Test Pad" "Test Point, SMT 1.5mm Round" 16.024,27.61 r270 bottom
TP9 "SMT, 1.5mm, Test Pad" "Test Point, SMT 1.5mm Round" 38.097,47.219 r180 bottom
TP10 "SMT, 1.5mm, Test Pad" "Test Point, SMT 1.5mm Round" 38.912,42.395 r180 bottom
TP11 "SMT, 1.5mm, Test Pad" "Test Point, SMT 1.5mm Round" 15.438,44.856 r180 bottom
TP12 "SMT, 1.5mm, Test Pad" "Test Point, SMT 1.5mm Round" 12.213,40.793 r270 bottom
TP13 "SMT, 1.5mm, Test Pad" "Test Point, SMT 1.5mm Round" 12.213,28.013 r270 bottom
TP14 "SMT, 1.5mm, Test Pad" "Test Point, SMT 1.5mm Round" 10.69,48.92 r0 bottom
TP15 "SMT, 1.5mm, Test Pad" "Test Point, SMT 1.5mm Round" 14.412,34.984 r90 bottom
TP16 "SMT, 1.5mm, Test Pad" "Test Point, SMT 1.5mm Round" 14.412,22.174 r90 bottom
TP17 "SMT, 1.5mm, Test Pad" "Test Point, SMT 1.5mm Round" 11.574,22.174 r90 bottom
TP18 "SMT, 1.5mm, Test Pad" "Test Point, SMT 1.5mm Round" 11.574,34.984 r90 bottom
TP19 "SMT, 1.5mm, Test Pad" "Test Point, SMT 1.5mm Round" 134.547,57.176 r90 bottom
TP20 "SMT, 1.5mm, Test Pad" "Test Point, SMT 1.5mm Round" 131.547,57.176 r90 bottom
TP21 "SMT, 0.7mm, Test Pad" "Test Point, SMT 0.7mm Round" 124.803,41.079 r180 bottom
TP22 "SMT, 0.7mm, Test Pad" "Test Point, SMT 0.7mm Round" 122.803,42.079 r180 bottom
TP23 "SMT, 0.7mm, Test Pad" "Test Point, SMT 0.7mm Round" 124.803,40.079 r180 bottom
TP24 "SMT, 0.7mm, Test Pad" "Test Point, SMT 0.7mm Round" 123.803,40.079 r180 bottom
TP25 "SMT, 0.7mm, Test Pad" "Test Point, SMT 0.7mm Round" 125.803,41.079 r180 bottom
TP26 "SMT, 0.7mm, Test Pad" "Test Point, SMT 0.7mm Round" 125.803,40.079 r180 bottom
TP27 "SMT, 0.7mm, Test Pad" "Test Point, SMT 0.7mm Round" 124.803,42.079 r180 bottom
TP28 "SMT, 0.7mm, Test Pad" "Test Point, SMT 0.7mm Round" 128.818,43.792 r180 bottom
TP29 "SMT, 0.7mm, Test Pad" "Test Point, SMT 0.7mm Round" 125.803,42.079 r180 bottom
TP30 "SMT, 0.7mm, Test Pad" "Test Point, SMT 0.7mm Round" 130.097,43.02 r180 bottom
TP31 "SMT, 0.7mm, Test Pad" "Test Point, SMT 0.7mm Round" 125.803,43.079 r180 bottom
TP32 "SMT, 0.7mm, Test Pad" "Test Point, SMT 0.7mm Round" 126.803,41.079 r180 bottom
TP33 "SMT, 0.7mm, Test Pad" "Test Point, SMT 0.7mm Round" 126.803,40.079 r180 bottom
TP34 "SMT, 0.7mm, Test Pad" "Test Point, SMT 0.7mm Round" 126.803,39.079 r180 bottom
TP35 "SMT, 1.5mm, Test Pad" "Test Point, SMT 1.5mm Round" 17.128,38.727 r270 top
TP36 "SMT, 1.5mm, Test Pad" "Test Point, SMT 1.5mm Round" 48.14,2.183 r270 bottom
TP37 "SMT, 1.5mm, Test Pad" "Test Point, SMT 1.5mm Round" 9.243,31.75 r270 bottom
TP38 "SMT, 1.5mm, Test Pad" "Test Point, SMT 1.5mm Round" 36.167,49.2 r0 bottom
TP39 "SMT, 1.5mm, Test Pad" "Test Point, SMT 1.5mm Round" 63.176,20.855 r0 top
TP40 "SMT, 1.5mm, Test Pad" "Test Point, SMT 1.5mm Round" 15.997,2 r90 bottom
TP41 "SMT, 1.5mm, Test Pad" "Test Point, SMT 1.5mm Round" 18.615,57.582 r270 bottom
TP42 "SMT, 1.5mm, Test Pad" "Test Point, SMT 1.5mm Round" 4.009,52.285 r270 bottom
